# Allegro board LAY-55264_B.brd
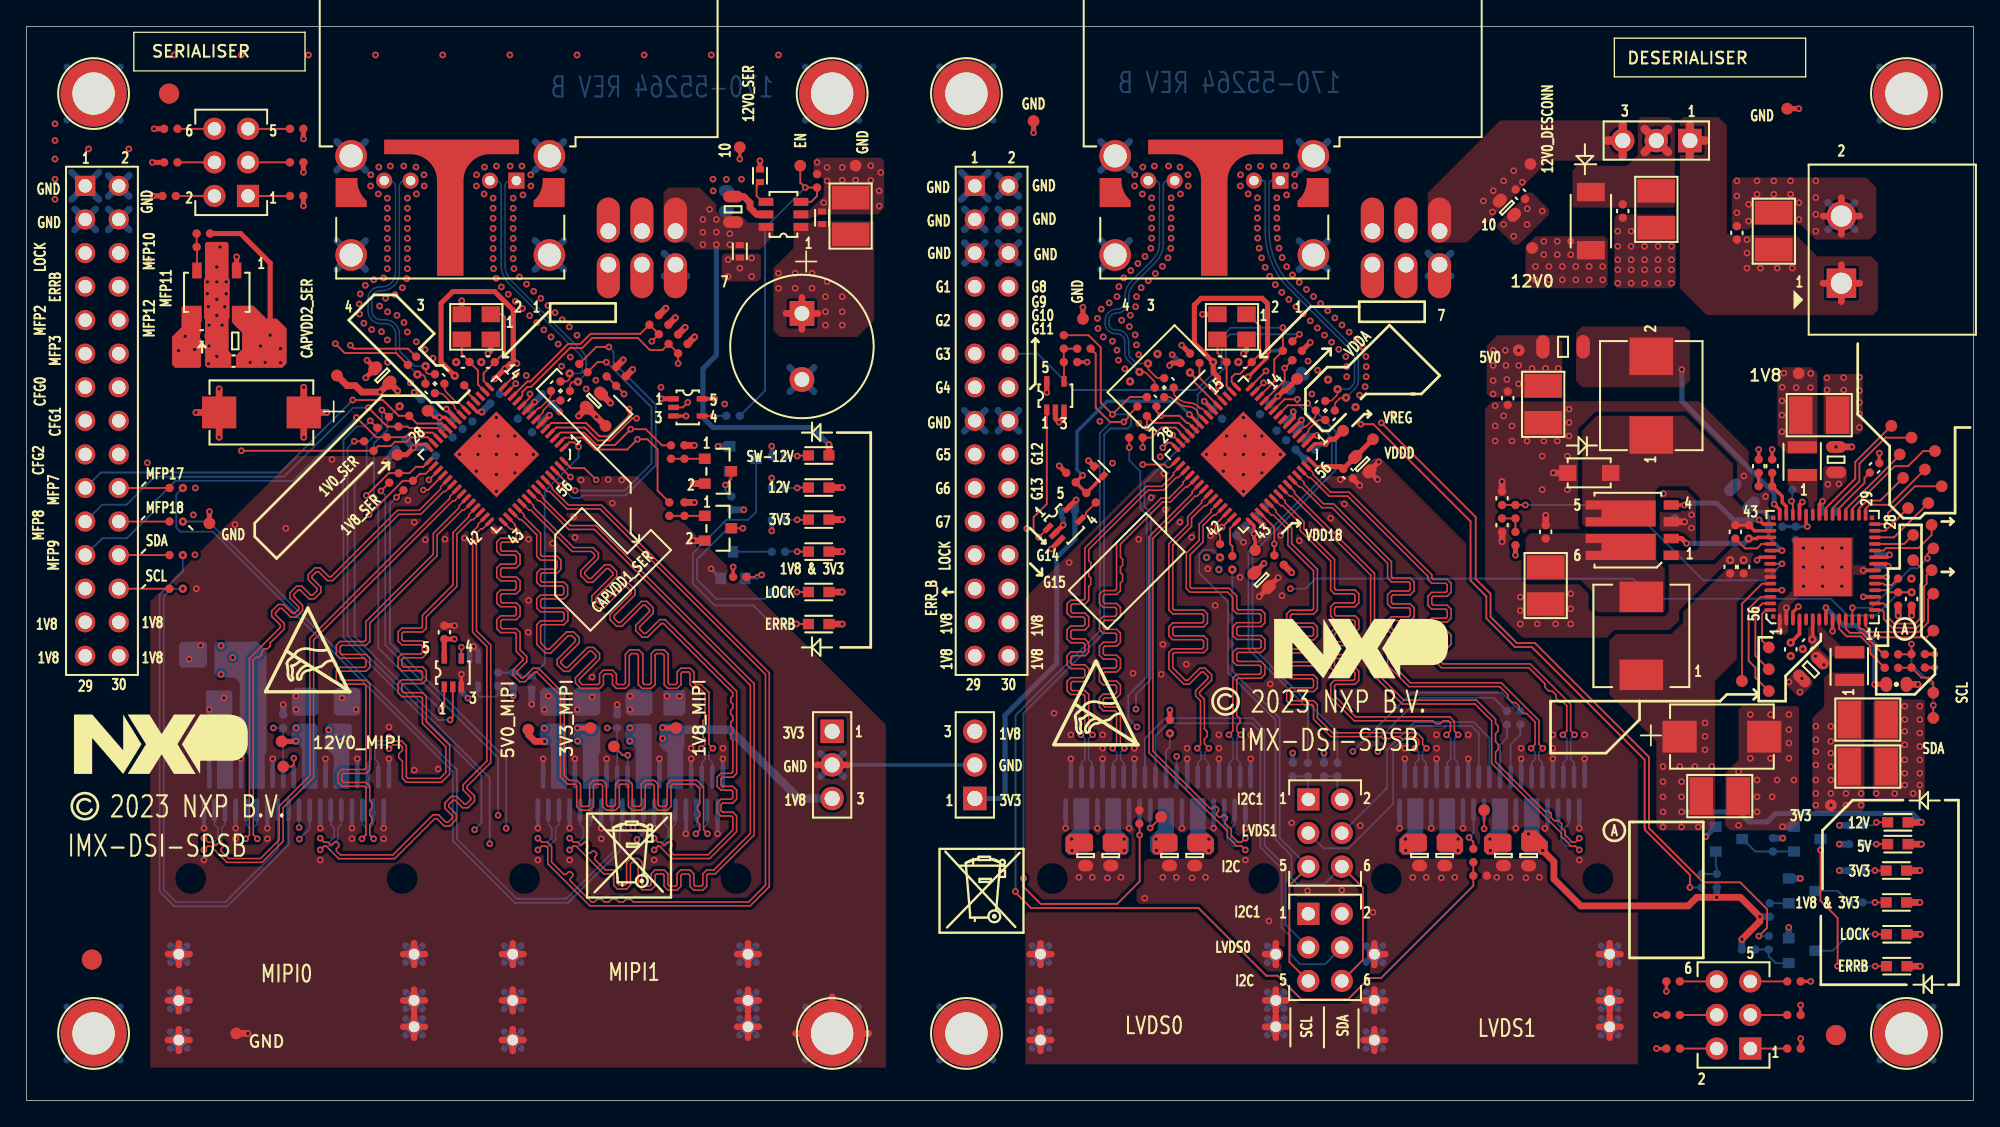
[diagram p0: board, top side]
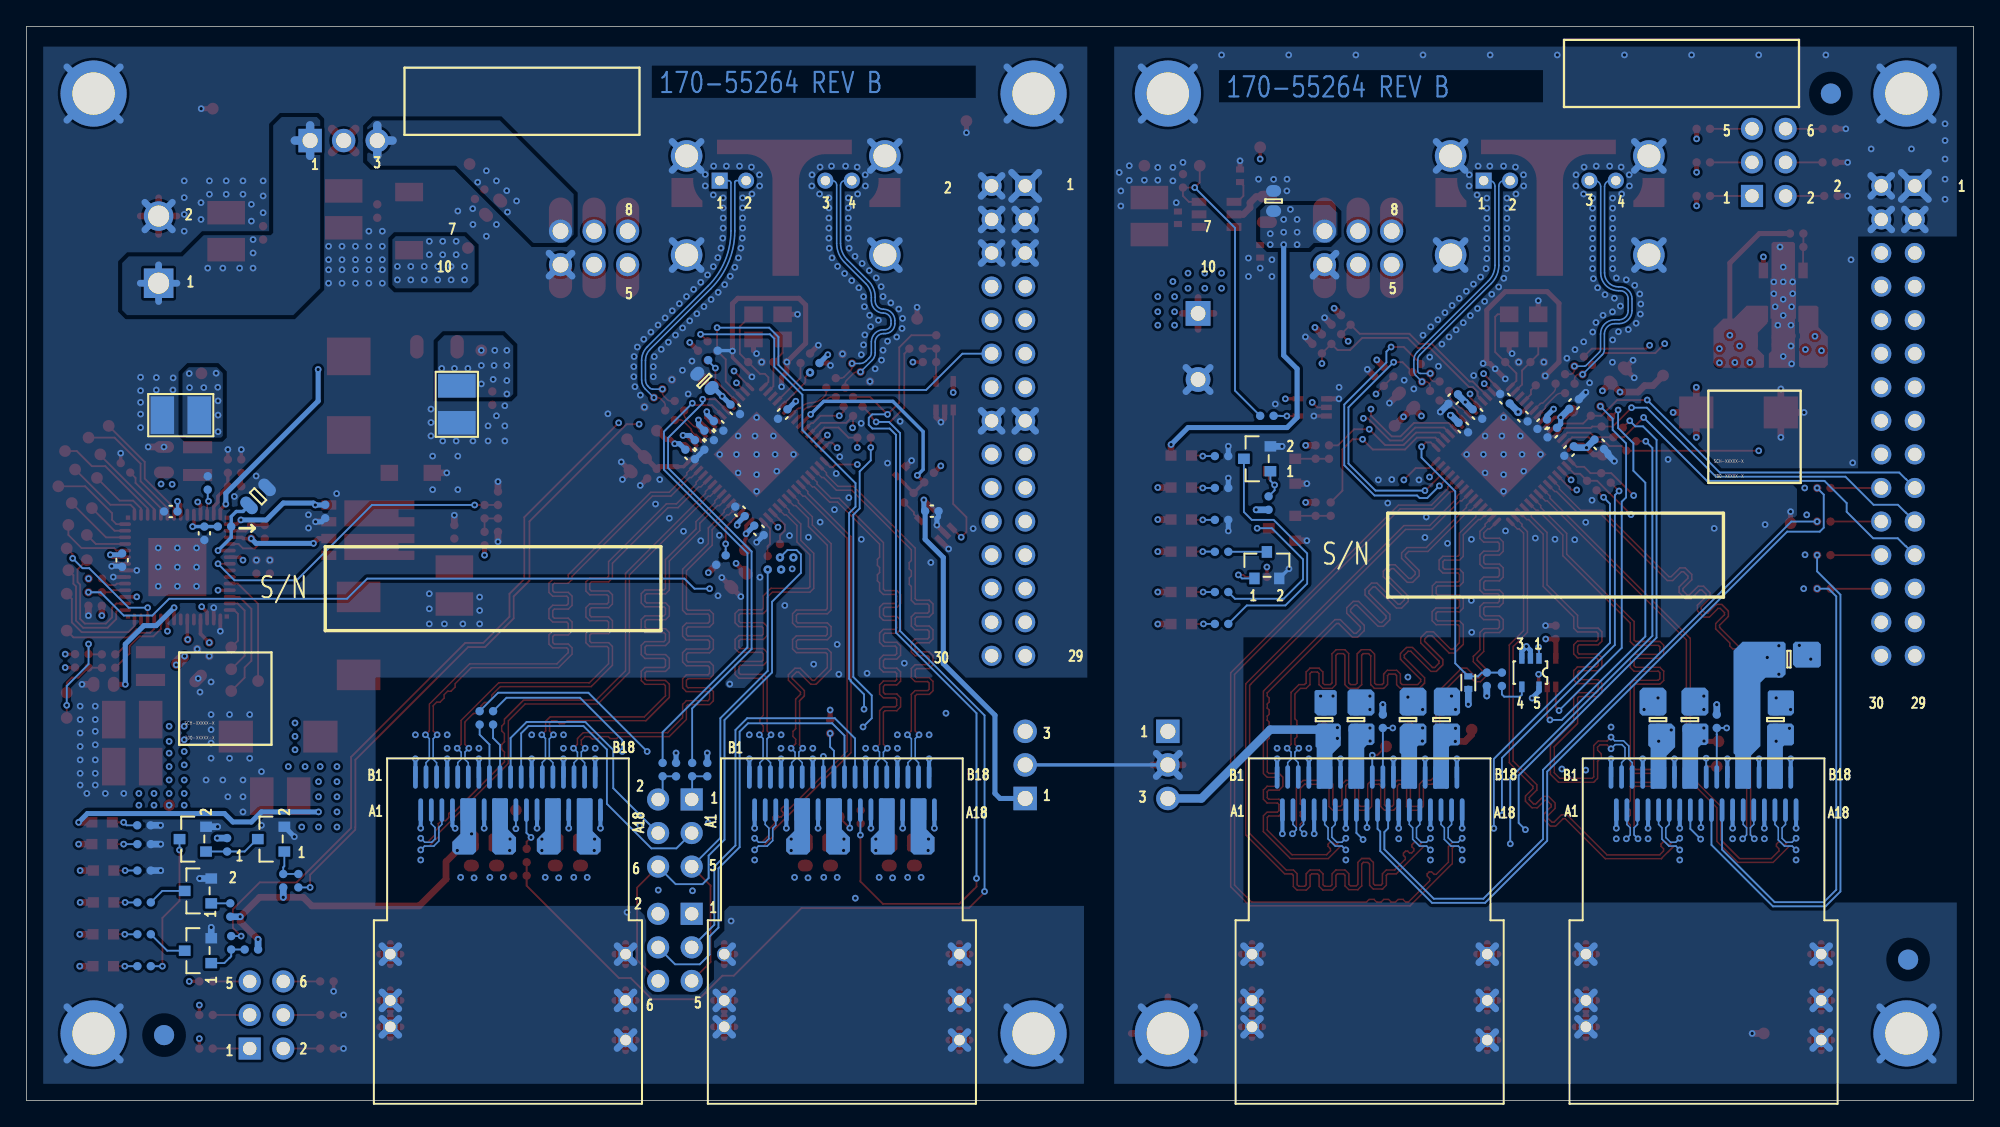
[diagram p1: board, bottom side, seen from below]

Outline 147.32 x 81.28 mm; copper layers: TOP, L2_GND_1, L3_MIX_1, L4_MIX_2, L5_GND_2, BOTTOM. Coordinates in mm from the lower left corner of the outline.
Outline path: 0,81.28 0,0 147.32,0 147.32,81.28 0,81.28

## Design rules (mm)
constraint set DEFAULT: min track width 0.137, pair gap 0.178
net group GMSL2_OUT0_N: nets GMSL2_OUT0_N
net group GMSL2_OUT0_P: nets GMSL2_OUT0_P
net group GMSL2_OUT1_N: nets GMSL2_OUT1_N
net group GMSL2_OUT1_P: nets GMSL2_OUT1_P
net group GRP_DSI0: nets MIPI_DSI0_CLK_N MIPI_DSI0_CLK_P MIPI_DSI0_DATA0_N MIPI_DSI0_DATA0_P MIPI_DSI0_DATA1_N MIPI_DSI0_DATA1_P MIPI_DSI0_DATA2_N MIPI_DSI0_DATA2_P MIPI_DSI0_DATA3_N MIPI_DSI0_DATA3_P
net group GRP_DSI1: nets MIPI_DSI1_CLK_N MIPI_DSI1_CLK_P MIPI_DSI1_DATA0_N MIPI_DSI1_DATA0_P MIPI_DSI1_DATA1_N MIPI_DSI1_DATA1_P MIPI_DSI1_DATA2_N MIPI_DSI1_DATA2_P MIPI_DSI1_DATA3_N MIPI_DSI1_DATA3_P
net group GRP_LVDS0: nets LVDS0_CH0_CLK_N LVDS0_CH0_CLK_P LVDS0_CH0_TX0_N LVDS0_CH0_TX0_P LVDS0_CH0_TX1_N LVDS0_CH0_TX1_P LVDS0_CH0_TX2_N LVDS0_CH0_TX2_P LVDS0_CH0_TX3_N LVDS0_CH0_TX3_P
net group GRP_LVDS1: nets LVDS0_CH1_CLK_N LVDS0_CH1_CLK_P LVDS0_CH1_TX0_N LVDS0_CH1_TX0_P LVDS0_CH1_TX1_N LVDS0_CH1_TX1_P LVDS0_CH1_TX2_N LVDS0_CH1_TX2_P LVDS0_CH1_TX3_N LVDS0_CH1_TX3_P
net group MAX96752_SIOA_N: nets GMSL2DES_OUT0_N
net group MAX96752_SIOB_N: nets GMSL2DES_OUT1_N
net group MAX96752_SIOB_P: nets GMSL2DES_OUT1_P
net group PWR: nets FS84_DBG MAX96789_CAPVDD1 MAX96789_CAPVDD2 VCC_3V3_MIPI VCC_5V0_MIPI VDDA_MAX96752 VDDD_MAX96752

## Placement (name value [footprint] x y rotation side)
BH1  MOUNTING HOLE  [MH_C197-126T]  142.24 5.08 0 top
BH2  MOUNTING HOLE  [MH_C197-126T]  142.24 76.2 0 top
BH3  MOUNTING HOLE  [MH_C197-126T]  5.08 76.2 0 top
BH4  MOUNTING HOLE  [MH_C197-126T]  60.96 76.2 0 top
BH5  MOUNTING HOLE  [MH_C197-126T]  71.12 76.2 0 top
BH6  MOUNTING HOLE  [MH_C197-126T]  5.08 5.08 0 top
BH7  MOUNTING HOLE  [MH_C197-126T]  71.12 5.08 0 top
BH8  MOUNTING HOLE  [MH_C197-126T]  60.96 5.08 0 top
C1  10uF  [CC0603_OV]  49.14 28.83 270 bottom
C2  10uF  [CC0603_OV]  42.79 28.83 270 bottom
C3  10uF  [CC0603_OV]  40.25 28.83 270 bottom
C4  10uF  [CC0603_OV]  46.73 28.83 270 bottom
C5  10uF  [CC0603_OV]  23.88 28.83 270 bottom
C6  10uF  [CC0603_OV]  13.97 33.4 0 bottom
C7  10uF  [CC0603_OV]  14.99 28.83 270 bottom
C8  10uF  [CC0603_OV]  21.46 28.83 270 bottom
C9  0.1uF  [CC0402_25]  31.26 54.61 315 top
C10  0.1uF  [CC0402_25]  30.55 53.89 315 top
C11  0.1uF  [CC0402_25]  40.05 54.05 225 top
C12  0.1uF  [CC0402_25]  40.76 53.34 225 top
C13  10uF  [CC0603_OV]  52.96 68.07 270 bottom
C14  0.1uF  [CC0402_25]  32.64 51.18 315 bottom
C15  10uF  [CC0603_OV]  26.92 54.86 315 top
C16  0.1uF  [CC0402_25]  38.61 50.93 225 bottom
C17  10uF  [CC0603_OV]  42.94 52.96 225 top
C18  15pF  [CC0402_25]  33.02 55.88 180 top
C19  15pF  [CC0402_25]  34.92 55.88 180 top
C20  0.01uF  [CC0402_25]  34.1 51.75 225 bottom
C21  0.1uF  [CC0402_25]  35.46 53.11 45 bottom
C22  0.01uF  [CC0402_25]  37.54 51.95 225 bottom
C23  0.1uF  [CC0402_25]  39.37 53.09 315 bottom
C24  0.01uF  [CC0402_25]  30.61 49.15 315 bottom
C25  0.1uF  [CC0402_25]  28.32 49.66 225 bottom
C26  0.1uF  [CC0402_25]  31.62 35.43 90 top
C27  1uF  [CC0402_TOL0P2]  38.23 31.62 270 bottom
C28  0.01uF  [CC0402_25]  31.88 50.55 315 bottom
C29  0.1uF  [CC0402_25]  30.23 52.7 135 bottom
C30  47uF  [CASE_D]  17.78 52.07 180 top
C31  0.01uF  [CC0402_25]  15.67 55.96 180 top
C32  4.7uF  [CC0805_OV]  15.8 57.48 180 top
C33  2.2uF  [CC0402_25]  13.26 57.86 0 top
C34  0.1uF  [CC0402_25]  86.44 54.31 315 top
C35  0.1uF  [CC0402_25]  85.73 53.59 315 top
C36  0.1uF  [CC0402_25]  97.91 52.58 225 top
C37  0.1uF  [CC0402_25]  98.63 51.86 225 top
C38  10uF  [CC0603_OV]  112.01 67.56 135 top
C39  0.1uF  [CC0402_25]  113.03 68.58 315 top
C40  0.1uF  [CC0402_25]  97.1 48.89 225 bottom
C41  0.1uF  [CC0402_25]  96.39 49.61 225 bottom
C42  0.1uF  [CC0402_25]  78.82 44.6 0 bottom
C43  15pF  [CC0402_25]  92.2 55.88 180 top
C44  15pF  [CC0402_25]  90.3 55.88 180 top
C45  1uF  [CC0402_TOL0P2]  81.15 47.62 135 top
C46  10uF  [CC0603_OV]  101.07 48.16 135 top
C47  0.1uF  [CC0402_25]  99.99 47.44 315 top
C48  10uF  [CC0603_OV]  96.03 54.46 225 bottom
C49  0.1uF  [CC0402_25]  93.69 52.31 225 bottom
C50  10uF  [CC0603_OV]  93.45 39.39 135 top
C51  0.01uF  [CC0402_25]  93.33 44.58 45 bottom
C52  0.01uF  [CC0402_25]  91.9 43.15 225 bottom
C53  0.01uF  [CC0402_25]  95.67 50.33 225 bottom
C54  0.01uF  [CC0402_25]  94.95 51.05 225 bottom
C55  0.01uF  [CC0402_25]  90.1 51.95 315 bottom
C56  10uF  [CC0603_OV]  113.66 18.54 90 top
C57  10uF  [CC0603_OV]  107.31 18.54 90 top
C58  10uF  [CC0603_OV]  105.4 18.54 90 top
C59  10uF  [CC0603_OV]  111.75 18.54 90 top
C60  10uF  [CC0603_OV]  88.39 18.54 90 top
C61  10uF  [CC0603_OV]  82.04 18.54 90 top
C62  10uF  [CC0603_OV]  80.14 18.54 90 top
C63  10uF  [CC0603_OV]  86.49 18.54 90 top
C64  10uF  [CC1210]  123.32 67.44 270 top
C65  0.1uF  [CC0402_25]  120.78 67.31 270 top
C66  10uF  [CC1210]  132.21 65.79 90 top
C67  0.1uF  [CC0402_25]  129.41 65.66 90 top
C68  47uF  [CASE_D]  128.28 27.54 0 top
C69  10uF  [CC1210]  128.12 23.04 0 top
C70  0.1uF  [CC0402_25]  128.91 40.39 90 top
C71  10uF  [CC1210]  114.95 38.97 270 top
C72  0.1uF  [CC0402_25]  114.95 43.04 90 top
C73  0.022uF  [CC0402_25]  111.64 43.54 270 top
C74  0.1uF  [CC0402_25]  111.64 45.58 90 top
C75  22uF  [CC1210]  114.76 52.68 270 bottom
C76  22uF  [CC1210]  114.76 52.68 270 top
C77  0.1uF  [CC0402_25]  112.07 53.15 270 top
C78  4.7uF  [CC0805_OV]  129.79 45.72 315 bottom
C79  0.047uF  [CC0402_25]  129.3 43.04 270 top
C80  1uF  [CC0402_TOL0P2]  60.2 66.8 270 top
C81  10uF  [CC1210]  62.36 66.93 90 top
C82  1000pF  [CC0402_25]  129.92 40.39 90 top
C83  1uF  [CC0402_TOL0P2]  55.5 69.98 90 top
C84  1uF  [CC0402_TOL0P2]  53.98 64.26 270 top
C85  150pF  [CC0402_25]  132.08 48.01 90 top
C86  470uF  [CAP_10P5_RAD]  58.67 59.56 270 top
C87  6800pF  [CC0402_25]  131.06 48.01 90 top
C90  0.1uF  [CC0402_25]  133.49 34.15 90 top
C91  22uF  [CC1210]  139.32 25.27 0 top
C92  22uF  [CC1210]  139.32 28.83 0 top
C93  0.1uF  [CC0402_25]  134.76 34.53 225 top
C94  1000pF  [CC0402_25]  133.86 42.93 270 bottom
C95  4.7uF  [CC0805_OV]  135.01 32.62 225 top
C96  22uF  [CC1210]  135.64 51.86 0 top
C97  22uF  [CC1210]  135.64 51.86 0 bottom
C98  1000pF  [CC0402_25]  139.83 47.88 45 top
C99  4.7uF  [CC0805_OV]  136.92 48.5 90 top
C100  0.1uF  [CC0402_25]  136.4 44.58 0 bottom
C105  0.1uF  [CC0402_25]  140.08 40.89 270 bottom
C106  1000pF  [CC0402_25]  142.63 37.96 90 top
D1  LED GREEN  [LED_0603]  59.94 38.48 180 top
D2  RED LED  [LED_0603]  59.94 36.06 180 top
D3  LED GREEN  [LED_0603]  141.51 12.58 180 top
D4  RED LED  [LED_0603]  141.51 10.17 180 top
D5  PMEG6045ETP  [SOD-128]  118.36 66.55 270 top
D6  NRVTS2H60ESFT3G  [SOD-123]  118.24 47.5 0 top
D7  LED GREEN  [LED_0603]  59.94 41.54 180 top
D8  LED GREEN  [LED_0603]  59.94 46.39 180 top
D9  LED GREEN  [LED_0603]  141.48 14.99 180 top
D10  LED GREEN  [LED_0603]  141.59 21.05 180 top
D11  LED GREEN  [LED_0603]  141.59 19.4 180 top
D12  LED GREEN  [LED_0603]  59.94 48.81 180 top
D13  LED GREEN  [LED_0603]  141.48 17.41 180 top
D14  LED GREEN  [LED_0603]  59.94 43.96 180 top
J1  CON 2X18  [CON2X18_RECEP_WSHELL_0P8_SM_RA]  20.43 12.82 180 bottom
J2  CON 2X18  [CON2X18_RECEP_WSHELL_0P8_SM_RA]  45.69 12.82 180 bottom
J3  99S2HG-40MT5-Z  [CON_99S2HG_40MT5_RA_TH]  37.07 69.61 0 top
J4  HDR_2X15_TH  [HDR215_A_338H]  4.44 69.22 0 top
J5  99S2HG-40MT5-Z  [CON_99S2HG_40MT5_RA_TH]  94.87 69.61 0 top
J6  HDR_2X15_TH  [HDR215_A_338H]  71.75 69.22 0 top
J7  CON 2X18  [CON2X18_RECEP_WSHELL_0P8_SM_RA]  85.62 12.82 180 bottom
J8  CON 2X18  [CON2X18_RECEP_WSHELL_0P8_SM_RA]  110.89 12.82 180 bottom
J9  HDR 1X3  [HDR103_A_344H]  125.86 72.64 270 top
J10  CON 1X2 TB  [CON_TB_1X2_5P08_RA_TH]  137.32 61.85 90 top
J11  HDR 1X3  [HDR103_A_344H]  60.96 27.94 0 top
J12  HDR 1X3  [HDR103_A_344H]  71.75 22.86 180 top
J13  HDR 2X3  [HDR203]  16.76 68.45 180 top
J14  HDR 2X3  [HDR203]  130.43 3.94 180 top
J15  HDR 2X3  [HDR203]  96.99 22.78 0 top
J16  HDR 2X3  [HDR203]  96.99 14.13 0 top
L1  1uH  [IND2_7P4X6P9_SM]  122.18 35.16 90 top
L2  4.7UH  [IND2_7P5X7]  122.94 53.34 90 top
L4  1uH  [IND2520]  137.93 32.88 90 top
L5  1uH  [IND2520]  134.37 48.39 90 top
NOREF  -  []  42.64 14.47 90 top
NOREF#2  -  []  54.59 5.58 90 top
NOREF#3  -  []  51.89 24.49 0 top
NOREF#4  -  []  157.48 55.88 0 top
NOREF#5  -  []  54.59 7.58 90 top
NOREF#6  -  []  80.82 47.96 0 top
NOREF#7  -  []  37.07 69.61 90 top
NOREF#8  -  []  76.72 11.08 90 top
NOREF#9  -  []  139.5 28.77 90 top
NOREF#10  -  []  95.59 -6.47 90 top
NOREF#11  -  []  53.98 63.79 90 top
NOREF#12  -  []  101.83 63.25 0 top
NOREF#13  -  []  106.91 63.25 90 top
NOREF#14  -  []  144.56 77.13 0 top
NOREF#15  -  []  78.62 21.98 0 top
NOREF#16  -  []  39.57 63.98 0 top
NOREF#17  -  []  39.09 24.49 90 top
NOREF#18  -  []  12.43 16.8 90 top
NOREF#19  -  []  137.93 31.83 90 top
NOREF#20  -  []  119.79 11.08 90 top
NOREF#21  -  []  67.91 14.47 90 top
NOREF#22  -  []  132.16 44.11 0 top
NOREF#23  -  []  102.89 16.8 90 top
NOREF#24  -  []  13.83 24.49 90 top
NOREF#25  -  []  83.02 47.45 90 top
NOREF#26  -  []  60.2 66.33 90 top
NOREF#27  -  []  117.49 21.98 0 top
NOREF#28  -  []  5.08 5.08 0 top
NOREF#29  -  []  117.01 68.55 0 top
NOREF#30  -  []  44.03 63.25 90 top
NOREF#31  -  []  104.29 24.49 0 top
NOREF#32  -  []  84.87 69.61 0 top
NOREF#33  -  []  37.69 16.8 90 top
NOREF#34  -  []  73.44 77.13 0 top
NOREF#35  -  []  147.53 45.83 90 top
NOREF#36  -  []  138.32 46.99 90 top
NOREF#37  -  []  139.08 31.48 0 top
NOREF#38  -  []  97.37 63.98 90 top
NOREF#39  -  []  38.23 31.15 90 top
NOREF#40  -  []  122.94 50.36 90 top
NOREF#41  -  []  81.82 47.45 0 top
NOREF#42  -  []  77.62 16.8 90 top
NOREF#43  -  []  11.53 11.08 90 top
NOREF#44  -  []  101.99 11.08 90 top
NOREF#45  -  []  101.83 63.25 90 top
NOREF#46  -  []  119.79 7.58 90 top
NOREF#47  -  []  127.3 -32.82 90 top
NOREF#48  -  []  120.85 -6.47 90 top
NOREF#49  -  []  13.21 80.26 0 top
NOREF#50  -  []  74.93 -34.29 0 top
NOREF#51  -  []  37.69 16.8 90 top
NOREF#52  -  []  120.62 41.89 90 top
NOREF#53  -  []  76.72 4.58 90 top
NOREF#54  -  []  119.79 5.58 90 top
NOREF#55  -  []  125.63 31.46 0 top
NOREF#56  -  []  12.43 16.8 90 top
NOREF#57  -  []  30.39 13.47 90 top
NOREF#58  -  []  137.32 66.93 0 top
NOREF#59  -  []  13.83 24.49 0 top
NOREF#60  -  []  42.64 32.4 90 top
NOREF#61  -  []  12.43 16.8 90 top
NOREF#62  -  []  73.44 6.01 0 top
NOREF#63  -  []  54.82 64.86 90 top
NOREF#64  -  []  38.69 21.98 0 top
NOREF#65  -  []  90.73 30.18 0 top
NOREF#66  -  []  37.69 16.8 90 top
NOREF#67  -  []  -20.32 -257.18 0 top
NOREF#68  -  []  108.6 -5.47 90 top
NOREF#69  -  []  77.62 16.8 0 top
NOREF#70  -  []  109.12 -6.47 90 top
NOREF#71  -  []  54.59 11.08 90 top
NOREF#72  -  []  4.42 22.25 0 top
NOREF#73  -  []  127.14 41.99 90 top
NOREF#74  -  []  95.59 -6.47 90 top
NOREF#75  -  []  90.11 57.6 90 top
NOREF#76  -  []  27.07 69.61 0 top
NOREF#77  -  []  39.09 24.49 0 top
NOREF#78  -  []  36.79 11.08 0 top
NOREF#79  -  []  -285.24 263.14 0 top
NOREF#80  -  []  0 0 0 top
NOREF#81  -  []  102.04 -32.82 90 top
NOREF#82  -  []  94.52 5.58 90 top
NOREF#83  -  []  55.66 13.47 90 top
NOREF#84  -  []  18.11 30.94 0 top
NOREF#85  -  []  122.18 32.21 90 top
NOREF#86  -  []  52.29 21.98 0 top
NOREF#87  -  []  29.33 7.58 90 top
NOREF#88  -  []  11.53 4.58 90 top
NOREF#89  -  []  118.72 78.16 0 top
NOREF#90  -  []  38.58 32.22 0 top
NOREF#91  -  []  94.52 11.08 90 top
NOREF#92  -  []  12.43 16.8 0 top
NOREF#93  -  []  76.72 11.08 0 top
NOREF#94  -  []  119.24 41.99 0 top
NOREF#95  -  []  94.52 7.58 90 top
NOREF#96  -  []  86.87 69.61 0 top
NOREF#97  -  []  37.47 62.38 90 top
NOREF#98  -  []  7.4 77.13 0 top
NOREF#99  -  []  57.05 69.38 90 top
NOREF#100  -  []  92.87 69.61 0 top
NOREF#101  -  []  139.64 36.63 90 top
NOREF#102  -  []  37.69 16.8 0 top
NOREF#103  -  []  13.43 21.98 0 top
NOREF#104  -  []  38.69 21.98 90 top
NOREF#105  -  []  37.69 16.8 90 top
NOREF#106  -  []  7.4 6.01 0 top
NOREF#107  -  []  3.61 24.71 0 top
NOREF#108  -  []  97.37 63.98 90 top
NOREF#109  -  []  80.17 75.35 0 top
NOREF#110  -  []  79.02 24.49 0 top
NOREF#111  -  []  66.04 81.28 0 top
NOREF#112  -  []  133.03 31.46 90 top
NOREF#113  -  []  109.12 -6.47 90 top
NOREF#114  -  []  36.79 4.58 90 top
NOREF#115  -  []  120.62 44.43 0 top
NOREF#116  -  []  0 0 0 top
NOREF#117  -  []  26.63 24.49 0 top
NOREF#118  -  []  134.38 -6.47 90 top
NOREF#119  -  []  95.28 62.38 90 top
NOREF#120  -  []  5.08 5.08 0 top
NOREF#121  -  [unnamed#2]  136.91 4.95 0 top
NOREF#122  -  []  12.43 16.8 90 top
NOREF#123  -  []  59.85 67.4 0 top
NOREF#124  -  []  92.22 21.98 0 top
NOREF#125  -  []  94.87 69.61 90 top
NOREF#126  -  []  135.52 46.99 0 top
NOREF#127  -  []  53.62 64.86 0 top
NOREF#128  -  []  119.71 64.55 90 top
NOREF#129  -  []  117.09 24.49 0 top
NOREF#130  -  []  147.53 58.13 90 top
NOREF#131  -  []  131.5 28.77 0 top
NOREF#132  -  []  35.07 69.61 0 top
NOREF#133  -  []  103.89 21.98 0 top
NOREF#134  -  []  108.6 -5.47 90 top
NOREF#135  -  []  -309.88 -258.44 0 top
NOREF#136  -  []  24.57 63.98 0 top
NOREF#137  -  []  63.28 77.13 0 top
NOREF#138  -  []  55.85 69.38 0 top
NOREF#139  -  []  36.79 11.08 90 top
NOREF#140  -  []  61.05 67.4 90 top
NOREF#141  -  []  83.34 -5.47 90 top
NOREF#142  -  []  69.09 12.7 0 top
NOREF#143  -  []  39.57 63.98 90 top
NOREF#144  -  []  134.37 47.34 90 top
NOREF#145  -  []  5.08 5.08 0 top
NOREF#146  -  []  97.37 63.98 0 top
NOREF#147  -  []  137.32 61.85 90 top
NOREF#148  -  []  42.42 15.37 0 top
NOREF#149  -  []  0 81.28 0 top
NOREF#150  -  []  77.75 26.92 0 top
NOREF#151  -  []  39.57 63.98 90 top
NOREF#152  -  []  29.33 5.58 90 top
NOREF#153  -  []  0 81.28 0 top
NOREF#154  -  [unnamed#2]  4.95 10.67 0 top
NOREF#155  -  []  118.22 50.51 0 top
NOREF#156  -  []  55.5 69.5 90 top
NOREF#157  -  []  124.44 43.8 90 top
NOREF#158  -  []  139.15 36.41 90 top
NOREF#159  -  []  94.41 31.95 0 top
NOREF#160  -  []  134.38 -6.47 90 top
NOREF#161  -  []  118.36 64.35 90 top
NOREF#162  -  []  32.94 57.6 90 top
NOREF#163  -  []  82.37 63.98 0 top
NOREF#164  -  []  22.37 75.35 0 top
NOREF#165  -  []  29.07 69.61 0 top
NOREF#166  -  []  141.88 31.48 90 top
NOREF#167  -  []  11.53 11.08 0 top
NOREF#168  -  []  27.03 21.98 0 top
NOREF#169  -  []  44.03 63.25 0 top
NOREF#170  -  []  83.34 -5.47 90 top
NOREF#171  -  []  103.89 21.98 90 top
NOREF#172  -  []  78.62 21.98 90 top
NOREF#173  -  []  147.32 0 90 top
NOREF#174  -  [unnamed#2]  10.79 76.2 0 top
NOREF#175  -  []  63.28 6.01 0 top
NOREF#176  -  []  67.91 32.4 90 top
NOREF#177  -  []  144.56 6.01 0 top
NOREF#178  -  []  118.22 45.81 90 top
NOREF#179  -  []  135.02 45.83 0 top
NOREF#180  -  []  91.82 24.49 0 top
NOREF#181  -  []  66.04 0 0 top
NOREF#182  -  []  29.33 11.08 90 top
NOREF#183  -  []  13.43 21.98 90 top
NOREF#184  -  []  49.11 63.25 90 top
NOREF#185  -  []  39.78 32.22 90 top
NOREF#186  -  []  118.72 73.08 180 bottom
NOREF#187  -  []  124.71 35.56 180 bottom
NOREF#188  -  []  44.32 38.1 180 bottom
NOREF#189  -  [unnamed#2]  136.91 4.95 180 bottom
NOREF#190  -  []  30.99 75.18 180 bottom
NOREF#191  -  [unnamed#2]  10.79 76.2 180 bottom
NOREF#192  -  [unnamed#2]  4.95 10.67 180 bottom
Q1  BSS138P  [SOT23_A]  52.32 43.31 270 top
Q2  BSS138P  [SOT23_A]  54.2 48.56 90 bottom
Q3  BSS138P  [SOT23_A]  52.32 47.62 270 top
Q4  BSS138P  [SOT23_A]  134.34 11.34 90 bottom
Q5  BSS138P  [SOT23_A]  134.73 19.78 90 bottom
Q6  BSS138P  [SOT23_A]  128.81 19.78 90 bottom
Q7  BUK9K25-40E  [LFPAK56_1P27_4P7X5P3]  121.17 43.16 180 top
Q8  BSS138P  [SOT23_A]  53.47 40.51 180 bottom
Q9  BSS138P  [SOT23_A]  134.34 15.86 90 bottom
R1  48.7K  [RC0402_25]  42.09 54.76 45 top
R2  42.2K  [RC0402_25]  41.47 55.38 45 top
R3  48.7K  [RC0402_25]  29.22 55.31 135 top
R4  42.2K  [RC0402_25]  29.84 55.93 135 top
R5  0  [RC0402_25]  26.9 50.55 135 top
R6  0  [RC0402_25]  25.91 49.53 135 top
R7  0  [RC0402_25]  28.88 46.54 225 top
R8  0  [RC0402_25]  27.81 47.12 225 top
R9  0  [RC0402_25]  11.33 46.35 0 top
R10  0  [RC0402_25]  11.33 41.27 0 top
R11  0  [RC0402_25]  11.33 43.81 0 top
R12  0  [RC0402_25]  11.33 38.73 0 top
R13  402  [RC0402_25]  32.77 54.48 135 top
R14  10.0K  [RC0402_25]  36.83 31.88 90 bottom
R15  0  [RC0402_25]  35.69 31.88 90 bottom
R16  10.0K  [RC0402_25]  44.26 55.16 225 top
R17  44.2K  [RC0402_25]  48.95 57.62 225 top
R18  10.0K  [RC0402_25]  47.49 59.07 225 top
R19  10.0K  [RC0402_25]  44.98 54.44 45 top
R20  56.2K  [RC0402_25]  49.66 56.9 45 top
R21  10.0K  [RC0402_25]  48.21 58.35 45 top
R22  14K  [RC0402_25]  13.39 65.61 180 top
R23  10.0K  [RC0402_25]  49.78 44.75 270 top
R24  10.0K  [RC0402_25]  49.78 49.07 270 top
R25  1.00k  [RC0402_25]  56.9 38.48 0 bottom
R26  1.00k  [RC0402_25]  56.9 36.07 0 bottom
R27  56K  [RC0402_25]  13.39 64.59 0 top
R28  10.0K  [RC0402_25]  53.34 45.21 90 bottom
R29  0  [RC0402_25]  48.64 44.75 270 top
R30  10.0K  [RC0402_25]  84.2 21.46 90 top
R31  0  [RC0402_25]  48.77 49.07 270 top
R33  0  [RC0402_25]  95.43 57.1 45 top
R34  0  [RC0402_25]  90.31 41.6 270 top
R35  0  [RC0402_25]  91.24 40.69 270 top
R36  10.0K  [RC0402_25]  79.03 47.14 315 top
R37  0  [RC0402_25]  80.55 45.61 135 top
R38  402  [RC0402_25]  88.39 56.17 135 top
R39  10.0K  [RC0402_25]  94.78 40.9 135 top
R40  10.0K  [RC0402_25]  96.14 56.38 225 top
R41  10.0K  [RC0402_25]  87.67 55.45 315 bottom
R42  10.0K  [RC0402_25]  94.78 40.9 315 bottom
R43  10.0K  [RC0402_25]  95.38 56.39 135 bottom
R44  10.0K  [RC0402_25]  87.67 55.45 135 top
R45  10.0K  [RC0402_25]  130.3 11.43 0 bottom
R46  10.0K  [RC0402_25]  127.89 16.64 90 bottom
R47  1.00k  [RC0402_25]  138.42 12.58 0 bottom
R48  1.00k  [RC0402_25]  138.42 10.17 0 bottom
R49  10.0K  [RC0402_25]  132.14 19.35 270 bottom
R50  0  [RC0402_25]  131.83 11.94 270 bottom
R51  0  [RC0402_25]  126.75 16.64 90 bottom
R52  0  [RC0402_25]  113.03 28.96 90 bottom
R53  0  [RC0402_25]  112.01 28.96 90 bottom
R54  0  [RC0402_25]  109.47 18.54 90 top
R57  0  [RC0402_25]  112.66 42.53 90 top
R58  5.1K  [RC0402_25]  112.66 44.56 90 top
R59  0.02  [RC1206_OV]  116.26 57.04 180 top
R60  1M  [RC0402_25]  130.31 43.04 270 top
R61  1M  [RC0402_25]  124.71 44.58 270 bottom
R62  10.0K  [RC0402_25]  132.33 43.43 0 bottom
R63  3.57k  [RC0402_25]  131.57 46.48 180 top
R64  22.1K  [RC0402_25]  133.6 46.74 90 bottom
R65  0  [RC0402_25]  141.11 32.75 180 top
R66  0  [RC0402_25]  141.11 33.76 180 top
R67  4.7K  [RC0402_25]  143.13 32.77 180 top
R68  4.7K  [RC0402_25]  143.13 33.78 180 top
R69  0  [RC0402_25]  53.47 51.82 0 bottom
R70  270  [RC0805_OV]  53.47 67.44 270 top
R71  10.0K  [RC0402_25]  19.43 28.7 90 bottom
R72  10.0K  [RC0402_25]  44.69 28.7 90 bottom
R73  4.7K  [RC0402_25]  86.51 28.3 90 top
R74  5.1K  [RC0402_25]  141.62 37.96 90 top
R75  5.1K  [RC0402_25]  142.11 39.5 180 top
R76  4.7K  [RC0402_25]  98.17 25.04 90 bottom
R77  4.7K  [RC0402_25]  95.81 25.04 90 bottom
R78  0  [RC0402_25]  85.14 52.88 135 top
R79  100K  [RC0603_OV]  141.48 31.5 180 top
R80  0  [RC0402_25]  84.42 52.16 135 top
R81  0  [RC0402_25]  27.78 51.36 135 top
R82  0  [RC0402_25]  28.6 52.18 135 top
R83  49.9K  [RC0402_25]  85.22 56.13 45 top
R84  49.9K  [RC0402_25]  83.86 54.77 225 top
R85  49.9K  [RC0402_25]  98.84 54.19 135 top
R86  49.9K  [RC0402_25]  100.2 52.83 315 top
R87  1.00k  [RC0402_25]  56.9 41.53 0 bottom
R88  1.00k  [RC0402_25]  53.98 39.62 180 top
R89  5.23K  [RC0402_25]  56.9 46.35 0 bottom
R90  1.00k  [RC0402_25]  138.42 14.99 0 bottom
R91  5.23K  [RC0402_25]  138.43 20.83 0 bottom
R92  1.00k  [RC0402_25]  131.9 14.42 270 bottom
R93  1.5K  [RC0402_25]  138.42 19.4 0 bottom
R94  5.23K  [RC0402_25]  56.9 48.77 0 bottom
R95  1.00k  [RC0402_25]  138.42 17.41 0 bottom
R96  1.00k  [RC0402_25]  56.9 43.94 0 bottom
R97  10.0K  [RC0402_25]  109.98 17.02 0 top
R98  1.00k  [RC0402_25]  20.45 68.45 180 top
R99  10.0K  [RC0402_25]  10.79 68.45 180 top
R100  1.00k  [RC0402_25]  20.45 70.99 180 top
R101  10.0K  [RC0402_25]  124.59 3.94 180 top
R102  10.0K  [RC0402_25]  124.59 6.48 180 top
R103  10.0K  [RC0402_25]  124.59 9.02 180 top
R104  1.00k  [RC0402_25]  133.73 3.94 180 top
R105  1.00k  [RC0402_25]  133.73 6.48 180 top
R106  1.00k  [RC0402_25]  133.73 9.02 180 top
R107  10.0K  [RC0402_25]  10.92 70.99 180 top
R108  1.00k  [RC0402_25]  20.45 73.53 180 top
R109  10.0K  [RC0402_25]  10.92 73.53 180 top
R110  0  [RC0402_25]  78.49 57.4 270 top
R111  0  [RC0402_25]  80.01 56.9 180 top
R112  1.00k  [RC0402_25]  78.99 55.88 0 top
R114  0  [RC0402_25]  83.95 50.16 180 top
R115  10.0K  [RC0402_25]  59.82 69.6 90 top
R116  4.7K  [RC0402_25]  89.8 41.1 180 bottom
R117  4.7K  [RC0402_25]  90.73 40.18 180 bottom
R118  0  [RC0402_25]  99.19 25.04 270 bottom
R119  0  [RC0402_25]  96.95 25.04 270 bottom
TP1  TP_35MIL  [TESTPOINT_35MIL]  101.88 50.04 135 top
TP2  TP_35MIL  [TESTPOINT_35MIL]  96.14 54.61 135 top
TP3  TP_35MIL  [TESTPOINT_35MIL]  113.79 70.87 90 top
TP4  TP_35MIL  [TESTPOINT_35MIL]  13.84 43.69 0 top
TP5  TP_35MIL  [TESTPOINT_35MIL]  113.92 64.52 0 top
TP6  TP_35MIL  [TESTPOINT_35MIL]  133.22 75.06 0 top
TP7  TP_35MIL  [TESTPOINT_35MIL]  15.88 5.08 0 top
TP8  TP_35MIL  [TESTPOINT_35MIL]  62.74 70.74 90 top
TP9  TP_35MIL  [TESTPOINT_35MIL]  76.2 74.12 0 top
TP10  TP_35MIL  [TESTPOINT_35MIL]  79.93 59.15 0 top
TP11  TP_35MIL  [TESTPOINT_35MIL]  112.9 56.77 270 top
TP13  TP_35MIL  [TESTPOINT_35MIL]  136.53 22.35 90 top
TP14  TP_35MIL  [TESTPOINT_35MIL]  134.08 55.03 45 top
TP15  TP_35MIL  [TESTPOINT_35MIL]  144.27 30.86 90 top
TP16  TP_35MIL  [TESTPOINT_35MIL]  53.98 72.14 180 top
TP17  TP_35MIL  [TESTPOINT_35MIL]  144.27 28.96 90 top
TP18  TP_35MIL  [TESTPOINT_35MIL]  30.35 52.2 135 top
TP19  TP_35MIL  [TESTPOINT_35MIL]  28.07 48.87 135 top
TP20  TP_35MIL  [TESTPOINT_35MIL]  43.81 51.05 135 top
TP21  TP_35MIL  [TESTPOINT_35MIL]  23.49 54.86 135 top
TP22  TP_35MIL  [TESTPOINT_35MIL]  92.96 41.66 135 top
TP23  TP_35MIL  [TESTPOINT_35MIL]  99.62 50.69 135 top
TP24  TP_35MIL  [TESTPOINT_35MIL]  58.55 70.74 180 top
TP25  TP_35MIL  [TESTPOINT_35MIL]  19.43 25.27 0 top
TP26  TP_35MIL  [TESTPOINT_35MIL]  85.85 21.46 0 top
TP27  TP_35MIL  [TESTPOINT_35MIL]  44.45 26.8 0 top
TP28  TP_35MIL  [TESTPOINT_35MIL]  110.29 21.98 0 top
TP29  TP_35MIL  [TESTPOINT_35MIL]  129.79 31.75 0 top
TP30  TP_35MIL  [TESTPOINT_35MIL]  131.83 30.99 0 top
TP31  TP_35MIL  [TESTPOINT_35MIL]  131.83 32.64 0 top
TP32  TP_35MIL  [TESTPOINT_35MIL]  131.83 34.29 0 top
TP33  TP_35MIL  [TESTPOINT_35MIL]  144.27 41.78 0 top
TP34  TP_35MIL  [TESTPOINT_35MIL]  144.27 35.56 0 top
TP35  TP_35MIL  [TESTPOINT_35MIL]  144.27 38.35 0 top
TP36  TP_35MIL  [TESTPOINT_35MIL]  144.15 40.13 0 top
TP37  TP_35MIL  [TESTPOINT_35MIL]  142.75 40.89 0 top
TP38  TP_35MIL  [TESTPOINT_35MIL]  144.15 43.56 0 top
TP39  TP_35MIL  [TESTPOINT_35MIL]  142.75 42.8 0 top
TP40  TP_35MIL  [TESTPOINT_35MIL]  143.89 45.21 0 top
TP41  TP_35MIL  [TESTPOINT_35MIL]  142.37 44.83 0 top
TP42  TP_35MIL  [TESTPOINT_35MIL]  144.91 46.48 0 top
TP43  TP_35MIL  [TESTPOINT_35MIL]  143.64 47.75 0 top
TP44  TP_35MIL  [TESTPOINT_35MIL]  141.99 47.12 0 top
TP45  TP_35MIL  [TESTPOINT_35MIL]  144.4 49.15 0 top
TP46  TP_35MIL  [TESTPOINT_35MIL]  141.73 48.89 0 top
TP47  TP_35MIL  [TESTPOINT_35MIL]  142.62 50.16 0 top
TP48  TP_35MIL  [TESTPOINT_35MIL]  141.1 51.05 0 top
TP49  TP_35MIL  [TESTPOINT_35MIL]  49.15 28.19 0 top
TP50  TP_35MIL  [TESTPOINT_35MIL]  42.67 28.19 0 top
TP51  TP_35MIL  [TESTPOINT_35MIL]  37.97 28.07 0 top
TP52  TP_35MIL  [TESTPOINT_35MIL]  19.3 27.18 0 top
U1  MAX96789GTN/V+T  [QFN56_0P5_8X8_EP4P6]  35.56 48.89 225 top
U2  74AUP1G32GW-Q100  [SC70-5]  32.26 32.38 0 top
U3  AP7361C  [SOT-89-5]  14.4 61.16 180 top
U4  MAX96752GTN/V+T  [QFN56_0P5_8X8_EP4P6]  92.08 48.89 225 top
U5  74AUP1G125GW  [SC70-5]  78.53 43.64 315 top
U6  PC33VR5500W5ES  [QFN56_0P5_8X8_EP4P39]  135.9 40.37 90 top
U7  74AUP1G125GW  [SC70-5]  77.85 53.34 0 top
U8  74AUP1G125GW  [SC70-5]  33.53 32.38 0 bottom
U9  74AUP1G125GW  [SC70-5]  50.04 52.45 270 top
U10  TPS22810DBVT  [SOT23-6]  57.28 67.06 90 top
X1  25 MHz  [OSC4_3P2X2P5_SM]  34.04 58.55 180 top
X2  25 MHz  [OSC4_3P2X2P5_SM]  91.21 58.55 180 top

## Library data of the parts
BH1-BH8 = MOUNT_HOLE
C1-C3 C5-C7 C14-C29 C31-C33 C39-C58 C60-C62 C64-C67 C69-C79 C81-C85 C87 C90-C100 C105 C106 = CAP_NP
C4 C8 C13 C38 C59 C63 C80 = CAP_NP: tolerance: 20%
C9-C12 C34-C37 = CAP_NP: signal model: CAP_NP_CC0402_25_DISCRETE_0.55MM_150-79461_0.1UF_0.1uF
C30 C68 C86 = CAP_POL
D1-D4 D7-D14 = LED
D5 D6 = DIODE_SCHTKY
J1 J2 J7 J8 = CON_2X18_SH6
J3 J5 = CON14_RA_TH
J4 J6 = CONN_HDR_15X2
J9 J11 J12 = CONN_HDR_3X1
J10 = CONN_HDR_1X2
J13-J16 = CONN_HDR_3X2
L1 = INDP: tolerance: 20%
L2 = INDUCTOR
L4 L5 = INDUCTOR: tolerance: 20%
Q1-Q6 Q8 Q9 = MOSFET_N
Q7 = NMOS_DUAL_8P
R1-R31 R33-R54 R57 R59-R73 R75-R112 R114-R119 = RES
R58 R74 = RES: tolerance: 5%
TP1-TP11 TP13-TP52 = T POINT R: Tolerance: TOLERANCE; User Part Number: 510-75618
U1 = MAX96789GTN
U2 = 74AUP1G32_5P
U3 = AP7361C_5P
U4 = MAX96752GTN
U5 U7-U9 = 1G125
U6 = VR5500_56P_EP_A
U10 = TPS22810_6P
X1 X2 = XTAL_4P_B

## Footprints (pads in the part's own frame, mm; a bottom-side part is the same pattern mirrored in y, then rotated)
CAP_10P5_RAD
  rect 1.88x1.88 hole 1.118: 1(0,0)
  round 1.88 hole 1.118: 2(5,0)
CASE_D
  rect 2.591x2.413 smd: 1(-3.2,0) 2(3.2,0)
CC0402_25
  round 0.635 smd: 1(-0.508,0) 2(0.508,0)
CC0402_TOL0P2
  rect 0.457x0.61 smd: 1(-0.475,0) 2(0.475,0)
CC0603_OV
  oval 0.889x1.143 smd: 1(-0.762,0) 2(0.762,0)
CC0805_OV
  oval 0.889x1.524 smd: 1(-0.965,0) 2(0.965,0)
CC1210
  rect 1.778x2.845 smd: 1(-1.397,0) 2(1.397,0)
CON2X18_RECEP_WSHELL_0P8_SM_RA
  round 0 hole 1.549 unplated: (-8,3.975) (8,3.975)
  round 1.092 hole 0.813: 1(-8.9,-1.745) 2(8.9,-1.745) 3(-8.9,-5.245) 4(8.9,-5.245) 5(-8.9,-7.245) 6(8.9,-8.245)
  oval 0.356x1.778 smd: A1(-6.6,9.155) A2(-5.8,9.155) A3(-5,9.155) A4(-4.2,9.155) A5(-3.4,9.155) A6(-2.6,9.155) A7(-1.8,9.155) A8(-1,9.155) A9(-0.2,9.155) A10(0.6,9.155) A11(1.4,9.155) A12(2.2,9.155) A13(3,9.155) A14(3.8,9.155) A15(4.6,9.155) A16(5.4,9.155) A17(6.2,9.155) A18(7,9.155) B1(-7,11.665) B2(-6.2,11.665) B3(-5.4,11.665) B4(-4.6,11.665) B5(-3.8,11.665) B6(-3,11.665) B7(-2.2,11.665) B8(-1.4,11.665) B9(-0.6,11.665) B10(0.2,11.665) B11(1,11.665) B12(1.8,11.665) B13(2.6,11.665) B14(3.4,11.665) B15(4.2,11.665) B16(5,11.665) B17(5.8,11.665) B18(6.6,11.665)
CON_99S2HG_40MT5_RA_TH
  rect 1.219x1.219 hole 0.711: 1(0,0)
  round 1.219 hole 0.711: 2(-2,0) 3(-8,0) 4(-10,0)
  oval 1.753x3.404 hole 1.194: 5(6.96,-6.36) 6(9.5,-6.36) 7(12.04,-6.36) 8(6.96,-3.82) 9(9.5,-3.82) 10(12.04,-3.82)
  round 2.388 hole 1.753: 11(2.5,1.87) 12(-12.5,1.87) 13(-12.5,-5.63) 14(2.5,-5.63)
CON_TB_1X2_5P08_RA_TH
  rect 2.235x2.235 hole 1.6: 1(0,0)
  round 2.235 hole 1.6: 2(5.08,0)
HDR103_A_344H
  rect 1.778x1.778 hole 1.143: 1(0,0)
  round 1.778 hole 1.143: 2(0,-2.54) 3(0,-5.08)
HDR203
  rect 1.676x1.676 hole 1.016: 1(0,0)
  round 1.676 hole 1.016: 2(2.54,0) 3(0,-2.54) 4(2.54,-2.54) 5(0,-5.08) 6(2.54,-5.08)
HDR215_A_338H
  rect 1.524x1.524 hole 1.016: 1(0,0)
  round 1.524 hole 1.016: 2(2.54,0) 3(0,-2.54) 4(2.54,-2.54) 5(0,-5.08) 6(2.54,-5.08) 7(0,-7.62) 8(2.54,-7.62) 9(0,-10.16) 10(2.54,-10.16) 11(0,-12.7) 12(2.54,-12.7) 13(0,-15.24) 14(2.54,-15.24) 15(0,-17.78) 16(2.54,-17.78) 17(0,-20.32) 18(2.54,-20.32) 19(0,-22.86) 20(2.54,-22.86) 21(0,-25.4) 22(2.54,-25.4) 23(0,-27.94) 24(2.54,-27.94) 25(0,-30.48) 26(2.54,-30.48) 27(0,-33.02) 28(2.54,-33.02) 29(0,-35.56) 30(2.54,-35.56)
IND2_7P4X6P9_SM
  rect 2.311x3.302 smd: 1(-2.95,0) 2(2.95,0)
IND2_7P5X7
  rect 2.845x3.302 smd: 1(-2.975,0) 2(2.975,0)
IND2520
  rect 0.914x2.21 smd: 1(-1.05,0) 2(1.05,0)
LED_0603
  rect 0.838x0.787 smd: A(-0.775,0) C(0.775,0)
LFPAK56_1P27_4P7X5P3
  rect 1.143x0.711 smd: 1(-3.275,1.905) 2(-3.275,0.635) 3(-3.275,-0.635) 4(-3.275,-1.905)
  custom 0.493x0.493 smd: 5(0.55,-1.27) 6(0.55,1.27)
MH_C197-126T
  round 5.004 hole 3.2: 1(0,0)
OSC4_3P2X2P5_SM
  rect 1.397x1.194 smd: 1(-1.1,-0.95) 2(1.1,-0.95) 3(1.1,0.95) 4(-1.1,0.95)
QFN56_0P5_8X8_EP4P6
  oval 0.838x0.279 smd: 1(-3.969,3.25) 14(-3.969,-3.25) 29(3.969,-3.25) 42(3.969,3.25)
  rect 0.838x0.279 smd: 2(-3.969,2.75) 3(-3.969,2.25) 4(-3.969,1.75) 5(-3.969,1.25) 6(-3.969,0.75) 7(-3.969,0.25) 8(-3.969,-0.25) 9(-3.969,-0.75) 10(-3.969,-1.25) 11(-3.969,-1.75) 12(-3.969,-2.25) 13(-3.969,-2.75) 30(3.969,-2.75) 31(3.969,-2.25) 32(3.969,-1.75) 33(3.969,-1.25) 34(3.969,-0.75) 35(3.969,-0.25) 36(3.969,0.25) 37(3.969,0.75) 38(3.969,1.25) 39(3.969,1.75) 40(3.969,2.25) 41(3.969,2.75)
  oval 0.279x0.838 smd: 15(-3.25,-3.969) 28(3.25,-3.969) 43(3.25,3.969) 56(-3.25,3.969)
  rect 0.279x0.838 smd: 16(-2.75,-3.969) 17(-2.25,-3.969) 18(-1.75,-3.969) 19(-1.25,-3.969) 20(-0.75,-3.969) 21(-0.25,-3.969) 22(0.25,-3.969) 23(0.75,-3.969) 24(1.25,-3.969) 25(1.75,-3.969) 26(2.25,-3.969) 27(2.75,-3.969) 44(2.75,3.969) 45(2.25,3.969) 46(1.75,3.969) 47(1.25,3.969) 48(0.75,3.969) 49(0.25,3.969) 50(-0.25,3.969) 51(-0.75,3.969) 52(-1.25,3.969) 53(-1.75,3.969) 54(-2.25,3.969) 55(-2.75,3.969)
  rect 4.597x4.597 smd: 57(0,0)
QFN56_0P5_8X8_EP4P39
  rect 0.33x0.33 smd: (-3.738,3.738) (-3.738,-3.738) (3.738,3.738) (3.738,-3.738)
  oval 0.914x0.279 smd: 1(-3.962,3.25) 2(-3.962,2.75) 3(-3.962,2.25) 4(-3.962,1.75) 5(-3.962,1.25) 6(-3.962,0.75) 7(-3.962,0.25) 8(-3.962,-0.25) 9(-3.962,-0.75) 10(-3.962,-1.25) 11(-3.962,-1.75) 12(-3.962,-2.25) 13(-3.962,-2.75) 14(-3.962,-3.25) 29(3.962,-3.25) 30(3.962,-2.75) 31(3.962,-2.25) 32(3.962,-1.75) 33(3.962,-1.25) 34(3.962,-0.75) 35(3.962,-0.25) 36(3.962,0.25) 37(3.962,0.75) 38(3.962,1.25) 39(3.962,1.75) 40(3.962,2.25) 41(3.962,2.75) 42(3.962,3.25)
  oval 0.279x0.914 smd: 15(-3.25,-3.962) 16(-2.75,-3.962) 17(-2.25,-3.962) 18(-1.75,-3.962) 19(-1.25,-3.962) 20(-0.75,-3.962) 21(-0.25,-3.962) 22(0.25,-3.962) 23(0.75,-3.962) 24(1.25,-3.962) 25(1.75,-3.962) 26(2.25,-3.962) 27(2.75,-3.962) 28(3.25,-3.962) 43(3.25,3.962) 44(2.75,3.962) 45(2.25,3.962) 46(1.75,3.962) 47(1.25,3.962) 48(0.75,3.962) 49(0.25,3.962) 50(-0.25,3.962) 51(-0.75,3.962) 52(-1.25,3.962) 53(-1.75,3.962) 54(-2.25,3.962) 55(-2.75,3.962) 56(-3.25,3.962)
  rect 4.394x4.394 smd: 57(0,0)
RC0402_25
  round 0.635 smd: 1(-0.508,0) 2(0.508,0)
RC0603_OV
  oval 0.889x1.143 smd: 1(-0.762,0) 2(0.762,0)
RC0805_OV
  oval 0.889x1.524 smd: 1(-0.965,0) 2(0.965,0)
RC1206_OV
  oval 1.016x1.778 smd: 1(-1.524,0) 2(1.524,0)
SC70-5
  rect 0.406x0.813 smd: 1(-0.65,-1.079) 2(0,-1.079) 3(0.65,-1.079) 4(0.65,1.079) 5(-0.65,1.079)
SOD-123
  rect 1.321x1.219 smd: A(-1.626,0) C(1.626,0)
SOD-128
  rect 1.397x2.108 smd: A(-2.2,0) C(2.2,0)
SOT23-6
  rect 0.61x1.118 smd: 1(-0.95,-1.321) 2(0,-1.321) 3(0.95,-1.321) 4(0.95,1.321) 5(0,1.321) 6(-0.95,1.321)
SOT23_A
  rect 0.787x0.889 smd: 1(-0.94,-1.003) 2(0.94,-1.003) 3(0,1.003)
SOT-89-5
  rect 0.711x1.194 smd: 1(-1.5,-1.65) 3(1.5,-1.65) 4(1.5,1.65) 5(-1.5,1.65)
  custom 0.482x0.482 smd: 2(0,-0.122)
TESTPOINT_35MIL
  round 0.889 smd: 1(0,0)
unnamed#2
  round 1.524 smd: (0,0)

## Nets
12V0SER_LOADSW_EN: R69.2 R115.1 TP24.1(TP) U10.3
GND: BH1.1 BH2.1 BH3.1 BH4.1 BH5.1 BH6.1 BH7.1 BH8.1 C1.1 C2.1 C3.1 C4.1 C5.1 C6.1 C7.1 C8.1 C13.1 C14.2 C15.1 C16.2 C17.1 C18.2 C19.2 C20.2 C21.2 C22.2 C23.2 C24.2 C25.2 C26.2 C27.2 C28.2 C29.2 C30.2 C31.2 C32.2 C33.2 C38.1 C39.2 C40.2 C41.2 C42.1 C43.2 C44.2 C45.2 C46.1 C47.2 C48.1 C49.2 C50.1 C51.2 C52.2 C53.2 C54.2 C55.2 C56.1 C57.1 C58.1 C59.1 C60.1 C61.1 C62.1 C63.1 C64.2 C65.2 C66.2 C67.2 C68.2 C69.2 C70.2 C71.2 C72.2 C73.2 C74.2 C75.2 C76.2 C77.2 C78.1 C80.1 C81.2 C82.2 C83.2 C84.2 C85.2 C86.2 C87.2 C90.1 C91.2 C92.2 C93.2 C94.2 C95.2 C96.2 C97.2 C98.2 C99.2 C100.2 C105.2 C106.1 D6.A J1.1 J1.2 J1.3 J1.4 J1.5 J1.6(SH6) J1.A1 J1.A4 J1.A7 J1.A12 J1.A15 J1.A18 J1.B1 J1.B4 J1.B7 J1.B12 J1.B15 J1.B18 J2.1 J2.2 J2.3 J2.4 J2.5 J2.6(SH6) J2.A1 J2.A4 J2.A7 J2.A12 J2.A15 J2.A18 J2.B1 J2.B4 J2.B7 J2.B12 J2.B15 J2.B18 J3.7 J3.11 J3.12 J3.13 J3.14(SH4) J4.1 J4.2 J4.3 J4.4 J5.7 J5.11 J5.12 J5.13 J5.14(SH4) J6.1 J6.2 J6.3 J6.4 J6.5 J6.6 J6.15 J6.16 J7.1 J7.2 J7.3 J7.4 J7.5 J7.6(SH6) J7.A1 J7.A4 J7.A7 J7.A12 J7.A15 J7.A18 J7.B1 J7.B4 J7.B7 J7.B12 J7.B15 J7.B18 J8.1 J8.2 J8.3 J8.4 J8.5 J8.6(SH6) J8.A1 J8.A4 J8.A7 J8.A12 J8.A15 J8.A18 J8.B1 J8.B4 J8.B7 J8.B12 J8.B15 J8.B18 J10.2(B1) J11.2 J12.2 Q1.2(SOURCE) Q2.2(SOURCE) Q3.2(SOURCE) Q4.2(SOURCE) Q5.2(SOURCE) Q6.2(SOURCE) Q7.3(SOURCE2) Q8.2(SOURCE) Q9.2(SOURCE) R13.2 R19.2 R20.2 R21.2 R27.2 R30.2 R38.2 R42.2 R43.2 R44.2 R61.2 R64.2 R71.2 R72.2 R79.1 R83.2 R84.2 R85.2 R86.2 R89.1 R91.1 R93.1 R94.1 R95.1 R96.1 R97.2 R99.2 R101.2 R102.2 R103.2 R107.2 R109.2 R115.2 TP4.1(TP) TP6.1(TP) TP7.1(TP) TP8.1(TP) TP9.1(TP) TP10.1(TP) U1.57 U2.3 U3.2 U4.57 U5.2 U5.3 U6.1(WAKE2) U6.2 U6.20 U6.21 U6.22 U6.57 U7.2 U7.3 U8.2 U8.3 U9.1 U9.3 U10.2 X1.2 X1.4 X2.2 X2.4
VCC_1V0_SER: C28.1 C29.1 C30.1 C31.1 C32.1 R22.1 TP18.1(TP) U1.23 U3.5(OUT)
VCC_1V8_LVDS: C40.1 C41.1 C50.2 C51.1 C52.1 C53.1 C54.1 C55.1 C56.2 C60.2 C96.1 C97.1 J6.27 J6.28 J6.29 J6.30 J7.A5 J7.A6 J8.A5 J8.A6 J12.3 L5.2 R36.1 R39.1 R40.1 R41.1 R45.1 R46.1 R73.2 R76.2 R77.2 R92.2 R104.1 R105.1 R106.1 R112.2 R116.2 R117.2 TP14.1(TP) TP22.1(TP) TP23.1(TP) U4.1 U4.2 U4.5 U4.6 U4.20 U4.43 U4.44 U6.17 U6.39
VCC_1V8_MIPI: C1.2 C5.2 C20.1 C21.1 C22.1 C23.1 C24.1 C25.1 C26.1 C33.1 J1.B5 J1.B6 J2.B5 J2.B6 J4.27 J4.28 J4.29 J4.30 J11.3 R14.1 R16.1 R17.1 R18.1 R23.1 R24.1 R88.2 R98.1 R100.1 R108.1 TP19.1(TP) TP49.1(TP) U1.9 U1.19 U1.28 U2.5 U3.1 U3.4 U8.5 U9.5
VCC_3V3_LVDS: C42.2 C57.2 C61.2 C90.2 C91.1 C92.1 C105.1 D3.A D4.A D9.A D13.A J7.A13 J7.A14 J8.A13 J8.A14 J12.1 L4.1 R49.1 R67.1 R68.1 R74.1 R75.1 TP13.1(TP) U5.5 U6.4 U6.9 U6.23 U7.5
VCC_3V3_MIPI: C2.2 C6.2 D1.A D2.A D7.A D14.A J1.B13 J1.B14 J2.B13 J2.B14 J11.1 R28.1 TP50.1(TP)
VCC_5V0_LVDS: C58.2 C62.2 C75.1 C76.1 C77.1 C93.1 C95.1 C99.1 C100.1 D11.A J7.A16 J7.A17 J8.A16 J8.A17 R59.2 TP11.1(TP) U6.3 U6.6 U6.36 U6.48 U6.53
VCC_5V0_MIPI: C3.2 C7.2 J1.B16 J1.B17 J2.B16 J2.B17 TP51.1(TP)
VCC_12V0: C64.1 C65.1 D5.A J9.2
VCC_12V0_DESCONN: C38.2 C39.1 J5.10 J9.3 TP3.1(TP)
VCC_12V0_EXT: C66.1 C67.1 J9.1 J10.1
VCC_12V0_LVDS: C59.2 C63.2 C68.1 C69.1 C70.1 C82.1 D5.C D10.A J7.A8 J7.A9 J8.A8 J8.A9 L1.1 R57.1 TP5.1(TP) U6.50 U6.51
VCC_12V0_MIPI: C4.2 C8.2 C80.2 C81.1 C86.1 D8.A J1.B8 J1.B9 J2.B8 J2.B9 TP52.1(TP) U10.1
VCC_12V0_SER: C13.2 C84.1 D12.A J3.10 R70.2 TP16.1(TP) U10.6(VOUT)
VDDA_MAX96752: C48.2 C49.1 TP2.1(TP) U4.10
VDDD_MAX96752: C46.2 C47.1 TP1.1(TP) U4.56
FS84_BUCK1_SW: L5.1 U6.37
FS84_BUCK3_SW: L4.2 U6.7
FS84_DBG: R79.2 U6.8
FS84_ERRMON: R64.1 U6.40
FS84_INTB: C98.1 U6.33
FS84_PRE_BOOT: C79.2 U6.46
FS84_PRE_COMP: C85.1 R63.1 U6.41
FS84_PRE_CSP: L2.2 R59.1 U6.42
FS84_PRE_GHS: Q7.2 R60.2 U6.45
FS84_PRE_GLS: Q7.4 R61.1 U6.43
FS84_PRE_SW: C79.1 D6.C L2.1 Q7.1 Q7.5 R60.1 U6.44
FS84_PSYNC: C94.1 R62.2 U6.38
FS84_SCL: R65.2 U6.10
FS84_SDA: R66.2 U6.11
FS84_VBOS: C78.2 R62.1 U6.47
FS84_WAKE1: C74.1 R58.2 U6.49
GMSL2_OUT0_N: C10.1 J3.4 R3.1
GMSL2_OUT0_P: C9.1 J3.3 R4.1
GMSL2_OUT1_N: C12.1 J3.1 R1.1
GMSL2_OUT1_P: C11.1 J3.2 R2.1
GMSL2DES_OUT0_N: C35.1 J5.4 R84.1
GMSL2DES_OUT0_P: C34.1 J5.3 R83.1
GMSL2DES_OUT1_N: C37.1 J5.1 R86.1
GMSL2DES_OUT1_P: C36.1 J5.2 R85.1
LDO_1V0_FB_SER: R22.2 R27.1 U3.3
LVDS0_BL_PWM: J7.B8 R52.2 R114.2
LVDS0_CH0_CLK_N: J7.A2 U4.35
LVDS0_CH0_CLK_P: J7.A3 U4.34
LVDS0_CH0_TS_SCL: J7.B11 J16.3
LVDS0_CH0_TS_SDA: J7.B10 J16.4
LVDS0_CH0_TX0_N: J7.B2 U4.39
LVDS0_CH0_TX0_P: J7.B3 U4.38
LVDS0_CH0_TX1_N: J7.B5 U4.37
LVDS0_CH0_TX1_P: J7.B6 U4.36
LVDS0_CH0_TX2_N: J7.B13 U4.33
LVDS0_CH0_TX2_P: J7.B14 U4.32
LVDS0_CH0_TX3_N: J7.B16 U4.31
LVDS0_CH0_TX3_P: J7.B17 U4.30
LVDS0_CH1_CLK_N: J8.A2 U4.51
LVDS0_CH1_CLK_P: J8.A3 U4.50
LVDS0_CH1_TS_SCL: J8.B11 J15.3
LVDS0_CH1_TS_SDA: J8.B10 J15.4
LVDS0_CH1_TX0_N: J8.B2 U4.55
LVDS0_CH1_TX0_P: J8.B3 U4.54
LVDS0_CH1_TX1_N: J8.B5 U4.53
LVDS0_CH1_TX1_P: J8.B6 U4.52
LVDS0_CH1_TX2_N: J8.B13 U4.49
LVDS0_CH1_TX2_P: J8.B14 U4.48
LVDS0_CH1_TX3_N: J8.B16 U4.47
LVDS0_CH1_TX3_P: J8.B17 U4.46
LVDS0_TS_INT: J7.B9 R33.2 R53.2 R73.1
LVDS_EN_1: J7.A11 R30.1 R78.2 R110.1
LVDS_EN_2: R54.1 R80.2 R97.1 R111.1
MAX96752_ERR_B: J6.25 R51.1 U4.14
MAX96752_GPIO01_I2CSEL: J6.7 R41.2 R44.1 U4.19
MAX96752_GPIO02_MS: J6.9 R39.2 R42.1 U4.45
MAX96752_GPIO03: R34.1 U4.40
MAX96752_GPIO04: J6.13 U4.41
MAX96752_GPIO05: R35.1 U4.42
MAX96752_GPIO06: J6.19 U4.27
MAX96752_GPIO07: J6.21 U4.28
MAX96752_GPIO08: J6.8 U4.29
MAX96752_GPIO09_CXTP: J6.10 R40.2 R43.1 U4.11
MAX96752_GPIO10: J6.12 R33.1 U4.12
MAX96752_GPIO11: J6.14 R78.1 U4.24
MAX96752_GPIO12: J6.18(B9) R80.1 U4.25
MAX96752_GPIO13: J6.20 R114.1 U4.26
MAX96752_GPIO14: R118.1 U4.8
MAX96752_GPIO15: R119.1 U4.9
MAX96752_LOCK: J6.23 R50.1 U4.13
MAX96752_PWDN_B: C45.1 R36.2 R37.2 U4.23
MAX96752_SCL: J15.1 J16.1 R77.1 R119.2
MAX96752_SCL1: J15.5 J16.5 R35.2 R117.1
MAX96752_SDA: J15.2 J16.2 R76.1 R118.2
MAX96752_SDA1: J15.6(B3) J16.6(B3) R34.2 R116.1
MAX96752_SIOA_N: C35.2 U4.22
MAX96752_SIOA_P: C34.2 U4.21
MAX96752_SIOB_N: C37.2 U4.3
MAX96752_SIOB_P: C36.2 U4.4
MAX96752_X1: C43.1 U4.15 X2.1
MAX96752_X2: C44.1 U4.16 X2.3
MAX96752_XRES: R38.1 U4.18(XRES)
MAX96789_CAPVDD1: C16.1 C17.2 TP20.1(TP) U1.6
MAX96789_CAPVDD2: C14.1 C15.2 TP21.1(TP) U1.22
MAX96789_CFG0: J4.13 R16.2 R19.1 U1.10
MAX96789_CFG1: J4.15 R17.2 R20.1 U1.11
MAX96789_CFG2: J4.17 R18.2 R21.1 U1.12
MAX96789_ERRB: J4.7 R31.1 U1.3
MAX96789_I2C-SCL: J4.26 R12.1 U1.14
MAX96789_I2C-SDA: J4.24 R10.1 U1.13
MAX96789_LMN0: R4.2 U1.31
MAX96789_LMN1: R3.2 U1.32
MAX96789_LMN2: R2.2 U1.53
MAX96789_LMN3: R1.2 U1.54
MAX96789_MFP2: J4.9 U1.4
MAX96789_MFP3: J4.11 U1.5
MAX96789_MFP7: J4.19 R82.1 U1.24
MAX96789_MFP8: J4.21 R81.1 U1.25
MAX96789_MFP9: J4.23 R5.1 U1.26
MAX96789_MFP10: J4.6 R6.1 U1.27
MAX96789_MFP11: J4.8 R8.1 U1.29
MAX96789_MFP12: J4.10 R7.1 U1.30
MAX96789_MFP17: J4.20 R9.1 U1.55
MAX96789_MFP18: J4.22 R11.1 U1.56
MAX96789_MS_LOCK: J4.5 R29.1 U1.2
MAX96789_PWDN_B: C27.1 R14.2 R15.2 U1.1(\\P\W\D\N)
MAX96789_SIOA_N: C10.2 U1.21
MAX96789_SIOA_P: C9.2 U1.20
MAX96789_SIOB_N: C12.2 U1.7
MAX96789_SIOB_P: C11.2 U1.8
MAX96789_XRES: R13.1 U1.18
MIPI_DSI0_1_EN: J1.B11 R71.1 R82.2 U2.1
MIPI_DSI0_BL_PWM: J1.A8 R8.2
MIPI_DSI0_CLK_N: J1.B2 U1.40
MIPI_DSI0_CLK_P: J1.B3 U1.39
MIPI_DSI0_DATA0_N: J1.A2 U1.38
MIPI_DSI0_DATA0_P: J1.A3 U1.37
MIPI_DSI0_DATA1_N: J1.A5 U1.42
MIPI_DSI0_DATA1_P: J1.A6 U1.41
MIPI_DSI0_DATA2_N: J1.A13 U1.34
MIPI_DSI0_DATA2_P: J1.A14 U1.33
MIPI_DSI0_DATA3_N: J1.A16 U1.36
MIPI_DSI0_DATA3_P: J1.A17 U1.35
MIPI_DSI0_TS_INT_B: J1.A9 R5.2
MIPI_DSI0_TS_SCL: J1.A11 R12.2
MIPI_DSI0_TS_SDA: J1.A10 R10.2
MIPI_DSI1_1_EN: J2.B11 R72.1 R81.2 U2.2
MIPI_DSI1_BL_PWM: J2.A8 R6.2
MIPI_DSI1_CLK_N: J2.B2 U1.46
MIPI_DSI1_CLK_P: J2.B3 U1.45
MIPI_DSI1_DATA0_N: J2.A2 U1.44
MIPI_DSI1_DATA0_P: J2.A3 U1.43
MIPI_DSI1_DATA1_N: J2.A5 U1.48
MIPI_DSI1_DATA1_P: J2.A6 U1.47
MIPI_DSI1_DATA2_N: J2.A13 U1.50
MIPI_DSI1_DATA2_P: J2.A14 U1.49
MIPI_DSI1_DATA3_N: J2.A16 U1.52
MIPI_DSI1_DATA3_P: J2.A17 U1.51
MIPI_DSI1_TS_INT_B: J2.A9 R7.2
MIPI_DSI1_TS_SCL: J2.A11 R11.2
MIPI_DSI1_TS_SDA: J2.A10 R9.2
MIPI_DSI_EN: U2.4(Y) U8.1 U9.2
PMIC_PG: C106.2 R74.2 U5.1 U6.18 U7.1
PRE_COMP_RC: C87.1 R63.2
SW_CT: C83.1 U10.4
SW_QOD: R70.1 U10.5
VPI: C71.1 C72.1 L1.2 Q7.6
N20060287: C19.1 U1.15 X1.1
N20060288: C18.1 U1.16 X1.3
N20069061: J8.B8 R52.1
N20069073: J8.B9 R53.1
N20082822: D1.C(CATHODE) R25.2
N20082834: Q1.3 R25.1
N20083165: D2.C(CATHODE) R26.2
N20083177: Q2.3 R26.1
N20083959: Q2.1 Q3.3 R28.2
N20084103: Q1.1 R23.2 R29.2
N20084118: Q3.1 R24.2 R31.2
N20098940: R37.1 U5.4(Y)
N20105492: D3.C(CATHODE) R47.2
N20105494: D4.C(CATHODE) R48.2
N20105548: Q4.3 R47.1
N20105560: Q5.3 R48.1
N20105562: Q4.1 R45.2 R50.2
N20105564: Q6.1 R46.2 R51.2
N20105588: Q5.1 Q6.3 R49.2
N20114256: C73.1 R57.2 R58.1
N20115373: R65.1 R67.2 TP15.1(TP)
N20115434: R66.1 R68.2 TP17.1(TP)
N20116336: R75.2 U6.19
N20169094: J8.A11 R54.2
N20198038: R15.1 U8.4(Y)
N20266401: J1.B10 TP25.1(TP)
N20266443: J2.B10 TP27.1(TP)
N20266627: J7.A10 TP26.1(TP)
N20266649: J8.A10 TP28.1(TP)
N20266684: TP29.1(TP) U6.52
N20266708: TP30.1(TP) U6.54
N20266714: TP31.1(TP) U6.55
N20267097: TP32.1(TP) U6.56
N20272842: D7.C(CATHODE) R87.2
N20272854: Q8.3 R87.1
N20272867: Q8.1 R88.1
N20273152: D8.C(CATHODE) R89.2
N20273623: D9.C(CATHODE) R90.2
N20273625: D10.C(CATHODE) R91.2
N20273637: Q9.3 R90.1
N20273680: Q9.1 R92.1
N20273951: D11.C(CATHODE) R93.2
N20274335: D12.C(CATHODE) R94.2
N20274920: D13.C(CATHODE) R95.2
N20275554: D14.C(CATHODE) R96.2
N20319150: J13.2 R99.1
N20319151: J13.4 R107.1
N20319153: J13.6(B3) R109.1
N20319312: J13.5 R108.2
N20319313: J13.3 R100.2
N20319314: J13.1 R98.2
N20319786: J14.1 R104.2
N20319788: J14.2 R101.1
N20319806: J14.3 R105.2
N20319808: J14.4 R102.1
N20319814: J14.5 R106.2
N20319816: J14.6(B3) R103.1
N20331689: R110.2 R111.2 R112.1 U7.4(Y)
N20347583: R69.1 U9.4(Y)
N2022936611: TP33.1(TP) U6.12
N2022936612: TP34.1(TP) U6.13
N2022936613: TP35.1(TP) U6.14
N2022936614: TP36.1(TP) U6.15
N2022936615: TP37.1(TP) U6.16
N2022936623: TP38.1(TP) U6.24
N2022936624: TP39.1(TP) U6.25
N2022936625: TP40.1(TP) U6.26
N2022936626: TP41.1(TP) U6.27
N2022936627: TP42.1(TP) U6.28
N2022936628: TP43.1(TP) U6.29
N2022936629: TP44.1(TP) U6.30
N2022936630: TP45.1(TP) U6.31
N2022936631: TP46.1(TP) U6.32
N2022936633: TP47.1(TP) U6.34
N2022936634: TP48.1(TP) U6.35

Pads without a net: J3 5 6 8 9; J4 12 14 16 18 25; J5 5 6 8 9; J6 11 17 22 24 26; U1 17; U4 7 17; U6 5

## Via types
v1: diameter 0.508, hole 0.257, TOP to BOTTOM, 89 vias
v2: diameter 0.508, hole 0.254, TOP to BOTTOM, 1020 vias

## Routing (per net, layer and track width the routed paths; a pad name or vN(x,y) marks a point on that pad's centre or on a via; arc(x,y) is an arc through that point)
12V0SER_LOADSW_EN: length 24.1
  TOP w0.137: TP24.1 58.55,69.47 v2(58.93,69.09) R115.1 59.82,68.45 59.37,68.01 U10.3
  BOTTOM w0.137: R69.2 55.88,53.72 55.88,66.04 v2(58.93,69.09)
GND: length 1454.1
  TOP w0.254: v2(93.9,56.72) 93.9,56.24 v2(92.43,54.76) ; R102.2 v2(123.33,6.48) ; R27.2 v2(14.64,64.59) ; C87.2 v2(131.06,49.26) ; R101.2 v2(123.33,3.94) ; U9.3 v2(49.91,51.8) ; C98.2 v2(140.19,48.99) ; C85.2 v2(132.08,49.26) ; R103.2 v2(124.08,8.27) ; U2.3 v2(32.91,32.26)
  TOP w0.279: v2(140.87,40.44) 140.69,40.62 U6.22 ; U6.21 v2(138.97,40.12) ; U6.20 v2(140.75,39.62) ; U6.2 v2(133.15,37.29) ; U6.1 v2(132.65,35.52)
  TOP w0.381: R107.2 v2(9.53,70.99) ; R38.2 v2(87.41,57.16) ; v2(34.92,56.52) 35.14,56.74 X1.4 ; X2.4 92.31,56.75 v2(92.08,56.52) ; X1.2 v2(32.94,60.53) ; R99.2 v2(9.54,68.45) ; v2(93.9,56.72) 93.9,60.3 93.5,60.71 88.87,60.71 88.37,60.2 88.37,57.3 v1(89.79,55.88) 89.79,55.12 90.19,54.72 v2(90.19,54.01) ; C26.2 v2(32.38,35.94) ; v2(25.68,54.69) C15.1 v2(25.77,56.02) ; U5.3 v2(77.55,41.74) ; C45.2 v2(80.35,48.43) ; v2(102.32,48.33) C46.1 v2(102.23,47) ; v2(94.71,39.57) C50.1 v2(93.27,38.14) ; R83.2 v1(85.58,56.5) ; X2.2 v2(88.98,59.5) ; TP9.1 v2(76.2,73.24) ; v1(32.41,54.84) 31.37,55.88 31.37,60.32 32.26,61.21 35.43,61.21 36.83,59.82 36.83,56.06 v2(37.11,55.78) 36.6,55.78 v2(36.2,55.37) v2(35.43,54.61) ; C47.2 v2(100.88,46.55) ; U9.1 v2(48.02,53.1) ; C83.2 v2(55.5,71.11) ; v2(86.49,55.63) 86.67,55.81 R44.2 ; TP4.1 v2(13.84,44.56) ; U5.2 v2(78.44,43.55) ; TP6.1 v2(134.1,75.06) ; U7.2 77.85,51.61 v2(78.13,51.33) 78.5,51.7 U7.3 ; R109.2 v2(9.66,73.53) ; TP10.1 v2(79.93,60.03)
  TOP w0.508: 36.79,10.27 J2.2 ; J2.2 35.98,11.08 ; J2.2 36.79,11.89 ; J2.2 37.61,11.08 ; C17.1 v2(44.2,52.78) ; J2.6 37.61,4.58 ; J2.6 35.98,4.58 ; J2.6 36.79,5.39 ; J2.6 36.79,3.77 ; J1.3 29.33,8.39 ; J1.3 28.52,7.58 ; J1.3 30.14,7.58 ; J1.3 29.33,6.77 ; R79.1 v2(143.12,31.5) ; J8.1 120.6,11.08 ; J8.1 118.97,11.08 ; J8.1 119.79,11.89 ; J8.1 119.79,10.27 ; 101.99,10.27 J8.2 ; J8.2 102.8,11.08 ; J8.2 101.99,11.89 ; J8.3 119.79,8.39 ; J8.3 118.97,7.58 ; J8.3 119.79,6.77 ; J8.3 120.6,7.58 ; 101.17,4.58 J8.6 ; J8.6 102.8,4.58 ; J8.6 101.99,3.77 ; J8.6 101.99,5.39 ; v1(136.92,49.46) v2(138.11,49.46) ; J7.4 76.72,8.39 ; J7.4 76.72,6.77 ; J7.4 75.91,7.58 ; J7.4 77.54,7.58 ; 59.8,25.4 J11.2 62.12,25.4 ; 28.52,11.08 J1.1 ; J1.1 29.33,11.89 ; J1.1 29.33,10.27 ; J1.1 30.14,11.08 ; J2.4 36.79,8.39 ; J2.4 35.98,7.58 ; J2.4 37.61,7.58 ; J2.4 36.79,6.77 ; 53.78,11.08 J2.1 ; J2.1 55.41,11.08 ; J2.1 54.59,11.89 ; J2.1 54.59,10.27 ; J7.6 77.54,4.58 ; J7.6 75.91,4.58 ; J7.6 76.72,3.77 ; J7.6 76.72,5.39 ; J1.5 30.14,5.58 ; J1.5 28.52,5.58 ; J1.5 29.33,4.77 ; J1.5 29.33,6.39 ; 54.59,4.77 J2.5 ; J2.5 55.41,5.58 ; J2.5 53.78,5.58 ; J2.5 54.59,6.39 ; J10.2 137.32,68.31 ; J10.2 135.93,66.93 ; J10.2 137.32,65.54 ; J10.2 138.71,66.93 ; 10.72,11.08 J1.2 ; J1.2 12.34,11.08 ; J1.2 11.53,11.89 ; J1.2 11.53,10.27 ; D6.A v2(115.52,47.5) ; BH8.1 60.96,7.85 ; BH8.1 63.73,5.08 ; BH8.1 58.19,5.08 ; 10.72,7.58 J1.4 ; J1.4 12.34,7.58 ; J1.4 11.53,6.77 ; J1.4 11.53,8.39 ; 101.99,6.77 J8.4 ; J8.4 101.99,8.39 ; J8.4 101.17,7.58 ; J8.4 102.8,7.58 ; C73.2 v2(111.64,42.29) ; J7.2 77.54,11.08 ; J7.2 76.72,10.27 ; J7.2 76.72,11.89 ; J7.2 75.91,11.08 ; 94.52,4.77 J7.5 ; J7.5 93.71,5.58 ; J7.5 94.52,6.39 ; J7.5 95.34,5.58 ; 118.97,5.58 J8.5 ; J8.5 119.79,6.39 ; J8.5 119.79,4.77 ; J8.5 120.6,5.58 ; R20.2 v2(50.55,57.79) ; J2.3 55.41,7.58 ; J2.3 53.78,7.58 ; J2.3 54.59,8.39 ; J2.3 54.59,6.77 ; J1.6 11.53,5.39 ; J1.6 12.34,4.58 ; J1.6 11.53,3.77 ; J1.6 10.72,4.58 ; J7.1 94.52,11.89 ; J7.1 94.52,10.27 ; J7.1 93.71,11.08 ; C72.2 v2(114.95,44.29) ; C74.2 v2(111.64,46.83) ; R21.2 v2(49.1,59.24) ; 94.52,6.77 J7.3 ; J7.3 94.52,8.39 ; J7.3 95.34,7.58 ; J7.3 93.71,7.58 ; R19.2 v2(45.87,55.33) ; Q1.2 v2(50.44,42.37) ; v2(14.58,53.85) C30.2 ; C30.2 v2(12.83,52.07) ; C30.2 v2(14.58,50.19) ; TP7.1 v2(16.75,5.08) ; C106.1 v2(142.63,36.7) ; Q7.3 v2(125.45,43.8) ; Q3.2 v2(50.44,46.69)
  L2_GND_1 w0.508: J5.7 107.73,64.07 ; J5.7 106.09,62.43 ; J5.7 106.09,64.07 ; J5.7 107.73,62.43 ; J2.6 37.38,5.16 ; J2.6 37.38,3.99 ; J2.6 36.21,3.99 ; J2.6 36.21,5.16 ; J5.12 83.41,70.44 ; J5.12 81.33,70.44 ; J5.12 81.33,72.53 ; J5.12 83.41,72.53 ; J3.13 25.61,62.94 ; J3.13 23.52,62.94 ; J3.13 25.61,65.03 ; J3.13 23.52,65.03 ; 96.33,72.53 J5.11 ; J5.11 98.42,72.53 ; J5.11 96.33,70.44 ; J5.11 98.42,70.44 ; BH3.1 7.05,74.23 ; BH3.1 3.11,78.17 ; BH3.1 7.05,78.17 ; BH3.1 3.11,74.23 ; BH2.1 144.21,74.23 ; BH2.1 140.27,74.23 ; BH2.1 140.27,78.17 ; BH2.1 144.21,78.17 ; 119.2,4.99 J8.5 ; J8.5 120.37,4.99 ; J8.5 119.2,6.16 ; J8.5 120.37,6.16 ; J6.4 75.03,67.41 ; J6.4 75.03,65.94 ; J6.4 73.56,67.41 ; J6.4 73.56,65.94 ; 96.33,65.03 J5.14 ; J5.14 98.42,62.94 ; J5.14 96.33,62.94 ; J5.14 98.42,65.03 ; J8.4 102.57,6.99 ; J8.4 102.57,8.16 ; J8.4 101.4,8.16 ; J8.4 101.4,6.99 ; J3.7 49.93,64.07 ; J3.7 48.29,64.07 ; J3.7 48.29,62.43 ; J3.7 49.93,62.43 ; J7.6 77.31,5.16 ; J7.6 76.14,5.16 ; J7.6 77.31,3.99 ; J7.6 76.14,3.99 ; J7.2 77.31,10.5 ; J7.2 76.14,11.66 ; J7.2 77.31,11.66 ; J7.2 76.14,10.5 ; 6.25,65.94 J4.4 ; J4.4 7.72,67.41 ; J4.4 7.72,65.94 ; J4.4 6.25,67.41 ; BH4.1 62.93,74.23 ; BH4.1 58.99,78.17 ; BH4.1 62.93,78.17 ; BH4.1 58.99,74.23 ; J2.2 37.38,11.66 ; J2.2 37.38,10.5 ; J2.2 36.21,10.5 ; J2.2 36.21,11.66 ; 119.2,8.16 J8.3 ; J8.3 120.37,8.16 ; J8.3 119.2,6.99 ; J8.3 120.37,6.99 ; J4.3 5.18,67.41 ; J4.3 5.18,65.94 ; J4.3 3.71,65.94 ; J4.3 3.71,67.41 ; 28.74,6.99 J1.3 ; J1.3 29.91,8.16 ; J1.3 29.91,6.99 ; J1.3 28.74,8.16 ; J7.4 77.31,6.99 ; J7.4 76.14,8.16 ; J7.4 76.14,6.99 ; J7.4 77.31,8.16 ; 69.15,74.23 BH5.1 ; BH5.1 73.09,78.17 ; BH5.1 69.15,78.17 ; BH5.1 73.09,74.23 ; 58.99,3.11 BH8.1 ; BH8.1 62.93,7.05 ; BH8.1 58.99,7.05 ; BH8.1 62.93,3.11 ; J2.3 55.18,8.16 ; J2.3 54.01,6.99 ; J2.3 55.18,6.99 ; J2.3 54.01,8.16 ; 101.4,5.16 J8.6 ; J8.6 102.57,3.99 ; J8.6 102.57,5.16 ; J8.6 101.4,3.99 ; 81.33,62.94 J5.13 ; J5.13 81.33,65.03 ; J5.13 83.41,62.94 ; J5.13 83.41,65.03 ; J1.6 12.11,3.99 ; J1.6 10.94,5.16 ; J1.6 10.94,3.99 ; J1.6 12.11,5.16 ; 10.94,8.16 J1.4 ; J1.4 12.11,6.99 ; J1.4 12.11,8.16 ; J1.4 10.94,6.99 ; J1.2 12.11,10.5 ; J1.2 10.94,10.5 ; J1.2 10.94,11.66 ; J1.2 12.11,11.66 ; J7.1 95.11,10.5 ; J7.1 93.94,10.5 ; J7.1 93.94,11.66 ; J7.1 95.11,11.66 ; J2.4 37.38,8.16 ; J2.4 37.38,6.99 ; J2.4 36.21,6.99 ; J2.4 36.21,8.16 ; J1.1 29.91,10.5 ; J1.1 28.74,11.66 ; J1.1 28.74,10.5 ; J1.1 29.91,11.66 ; 73.56,52.17 J6.16 ; J6.16 75.03,52.17 ; J6.16 73.56,50.7 ; J6.16 75.03,50.7 ; J6.3 72.49,67.41 ; J6.3 71.02,65.94 ; J6.3 71.02,67.41 ; J6.3 72.49,65.94 ; J4.1 5.18,68.48 ; J4.1 3.71,69.95 ; J4.1 5.18,69.95 ; J4.1 3.71,68.48 ; J11.2 61.79,26.23 ; J11.2 61.79,24.57 ; J11.2 60.13,26.23 ; J11.2 60.13,24.57 ; BH6.1 7.05,7.05 ; BH6.1 7.05,3.11 ; BH6.1 3.11,3.11 ; BH6.1 3.11,7.05 ; BH1.1 144.21,3.11 ; BH1.1 144.21,7.05 ; BH1.1 140.27,3.11 ; BH1.1 140.27,7.05 ; J6.6 75.03,63.4 ; J6.6 73.56,63.4 ; J6.6 73.56,64.87 ; J6.6 75.03,64.87 ; 69.15,7.05 BH7.1 ; BH7.1 73.09,7.05 ; BH7.1 73.09,3.11 ; BH7.1 69.15,3.11 ; J10.2 138.31,67.92 ; J10.2 136.33,65.94 ; J10.2 138.31,65.94 ; J10.2 136.33,67.92 ; J8.2 102.57,10.5 ; J8.2 101.4,10.5 ; J8.2 101.4,11.66 ; J8.2 102.57,11.66 ; J6.5 72.49,63.4 ; J6.5 72.49,64.87 ; J6.5 71.02,63.4 ; J6.5 71.02,64.87 ; 23.52,70.44 J3.12 ; J3.12 25.61,70.44 ; J3.12 23.52,72.53 ; J3.12 25.61,72.53 ; 119.2,10.5 J8.1 ; J8.1 119.2,11.66 ; J8.1 120.37,11.66 ; J8.1 120.37,10.5 ; 71.02,52.17 J6.15 ; J6.15 72.49,50.7 ; J6.15 71.02,50.7 ; J6.15 72.49,52.17 ; 28.74,6.16 J1.5 ; J1.5 28.74,4.99 ; J1.5 29.91,4.99 ; J1.5 29.91,6.16 ; J2.1 55.18,10.5 ; J2.1 54.01,11.66 ; J2.1 54.01,10.5 ; J2.1 55.18,11.66 ; 93.94,6.99 J7.3 ; J7.3 95.11,8.16 ; J7.3 93.94,8.16 ; J7.3 95.11,6.99 ; 93.94,4.99 J7.5 ; J7.5 93.94,6.16 ; J7.5 95.11,6.16 ; J7.5 95.11,4.99 ; J12.2 72.58,26.23 ; J12.2 72.58,24.57 ; J12.2 70.93,26.23 ; J12.2 70.93,24.57 ; 6.25,68.48 J4.2 ; J4.2 7.72,68.48 ; J4.2 7.72,69.95 ; J4.2 6.25,69.95 ; J6.1 72.49,69.95 ; J6.1 71.02,69.95 ; J6.1 71.02,68.48 ; J6.1 72.49,68.48 ; J3.14 40.61,62.94 ; J3.14 38.52,65.03 ; J3.14 38.52,62.94 ; J3.14 40.61,65.03 ; 38.52,72.53 J3.11 ; J3.11 38.52,70.44 ; J3.11 40.61,72.53 ; J3.11 40.61,70.44 ; J2.5 55.18,4.99 ; J2.5 55.18,6.16 ; J2.5 54.01,4.99 ; J2.5 54.01,6.16 ; 57.81,55.43 C86.2 ; C86.2 59.54,55.43 ; C86.2 59.54,53.7 ; C86.2 57.81,53.7 ; J6.2 75.03,69.95 ; J6.2 73.56,69.95 ; J6.2 73.56,68.48 ; J6.2 75.03,68.48
  L3_MIX_1 w0.508: J6.15 72.71,51.43 ; J6.15 71.75,50.48 ; J6.15 71.75,52.39 ; J6.15 70.8,51.43 ; 74.3,65.72 J6.4 ; J6.4 75.25,66.67 ; J6.4 73.34,66.67 ; J6.4 74.3,67.63 ; 73.34,69.22 J6.2 ; J6.2 74.3,70.17 ; J6.2 74.3,68.26 ; J6.2 75.25,69.22 ; 76.72,6.84 J7.4 ; J7.4 77.46,7.58 ; J7.4 76.72,8.32 ; J7.4 75.99,7.58 ; 119.05,7.58 J8.3 ; J8.3 120.53,7.58 ; J8.3 119.79,6.84 ; J8.3 119.79,8.32 ; 73.34,64.14 J6.6 ; J6.6 74.3,65.09 ; J6.6 75.25,64.14 ; J6.6 74.3,63.18 ; 49.11,62.18 J3.7 ; J3.7 48.04,63.25 ; J3.7 50.17,63.25 ; 93.79,5.58 J7.5 ; J7.5 95.26,5.58 ; J7.5 94.52,4.84 ; J7.5 94.52,6.32 ; 74.3,50.48 J6.16 ; J6.16 73.34,51.43 ; J6.16 75.25,51.43 ; J6.16 74.3,52.39 ; J3.13 25.95,63.98 ; J3.13 23.18,63.98 ; J3.13 24.57,62.6 ; J3.13 24.57,65.37 ; 38.18,63.98 J3.14 ; J3.14 39.57,65.37 ; J3.14 39.57,62.6 ; J3.14 40.95,63.98 ; 119.79,4.84 J8.5 ; J8.5 119.05,5.58 ; J8.5 120.53,5.58 ; J8.5 119.79,6.32 ; 95.99,63.98 J5.14 ; J5.14 98.76,63.98 ; J5.14 97.37,65.37 ; J5.14 97.37,62.6 ; 105.84,63.25 J5.7 ; J5.7 106.91,64.32 ; J5.7 107.98,63.25 ; J5.7 106.91,62.18 ; J6.5 72.71,64.14 ; J6.5 71.75,65.09 ; J6.5 70.8,64.14 ; J6.5 71.75,63.18 ; J6.1 72.71,69.22 ; J6.1 70.8,69.22 ; J6.1 71.75,70.17 ; J6.1 71.75,68.26 ; 137.32,65.62 J10.2 ; J10.2 138.63,66.93 ; J10.2 136.01,66.93 ; J10.2 137.32,68.24 ; J3.12 24.57,72.87 ; J3.12 25.95,71.48 ; J3.12 23.18,71.48 ; J3.12 24.57,70.1 ; J4.1 5.4,69.22 ; J4.1 3.49,69.22 ; J4.1 4.44,68.26 ; J4.1 4.44,70.17 ; J7.6 77.46,4.58 ; J7.6 76.72,3.84 ; J7.6 75.99,4.58 ; J7.6 76.72,5.32 ; 5.08,73.51 BH3.1 ; BH3.1 2.39,76.2 ; BH3.1 7.77,76.2 ; BH3.1 5.08,78.89 ; J8.4 102.73,7.58 ; J8.4 101.99,8.32 ; J8.4 101.25,7.58 ; J8.4 101.99,6.84 ; 97.37,70.1 J5.11 ; J5.11 98.76,71.48 ; J5.11 97.37,72.87 ; J5.11 95.99,71.48 ; 80.99,63.98 J5.13 ; J5.13 82.37,62.6 ; J5.13 82.37,65.37 ; J5.13 83.76,63.98 ; BH1.1 144.93,5.08 ; BH1.1 142.24,7.77 ; BH1.1 139.55,5.08 ; BH1.1 142.24,2.39 ; BH5.1 73.81,76.2 ; BH5.1 71.12,73.51 ; BH5.1 68.43,76.2 ; BH5.1 71.12,78.89 ; 71.12,2.39 BH7.1 ; BH7.1 68.43,5.08 ; BH7.1 71.12,7.77 ; BH7.1 73.81,5.08 ; 80.99,71.48 J5.12 ; J5.12 82.37,70.1 ; J5.12 82.37,72.87 ; J5.12 83.76,71.48 ; J7.3 94.52,8.32 ; J7.3 95.26,7.58 ; J7.3 93.79,7.58 ; J7.3 94.52,6.84 ; J6.3 71.75,67.63 ; J6.3 70.8,66.67 ; J6.3 71.75,65.72 ; J6.3 72.71,66.67 ; J3.11 40.95,71.48 ; J3.11 39.57,70.1 ; J3.11 39.57,72.87 ; J3.11 38.18,71.48 ; 6.03,69.22 J4.2 ; J4.2 7.94,69.22 ; J4.2 6.98,68.26 ; J4.2 6.98,70.17 ; BH2.1 142.24,78.89 ; BH2.1 144.93,76.2 ; BH2.1 139.55,76.2 ; BH2.1 142.24,73.51 ; 101.25,4.58 J8.6 ; J8.6 101.99,5.32 ; J8.6 102.73,4.58 ; J8.6 101.99,3.84
  L4_MIX_2 w0.508: 58.99,78.17 BH4.1 ; BH4.1 62.93,78.17 ; BH4.1 62.93,74.23 ; BH4.1 58.99,74.23 ; J10.2 138.31,67.92 ; J10.2 138.31,65.94 ; J10.2 136.33,65.94 ; J10.2 136.33,67.92 ; J3.14 40.61,65.03 ; J3.14 40.61,62.94 ; J3.14 38.52,65.03 ; J3.14 38.52,62.94 ; 140.27,74.23 BH2.1 ; BH2.1 140.27,78.17 ; BH2.1 144.21,78.17 ; BH2.1 144.21,74.23 ; 96.33,62.94 J5.14 ; J5.14 98.42,62.94 ; J5.14 98.42,65.03 ; J5.14 96.33,65.03 ; J5.13 83.41,65.03 ; J5.13 81.33,65.03 ; J5.13 81.33,62.94 ; J5.13 83.41,62.94 ; J5.12 83.41,70.44 ; J5.12 83.41,72.53 ; J5.12 81.33,72.53 ; J5.12 81.33,70.44 ; 23.52,65.03 J3.13 ; J3.13 25.61,65.03 ; J3.13 25.61,62.94 ; J3.13 23.52,62.94 ; 23.52,72.53 J3.12 ; J3.12 25.61,72.53 ; J3.12 25.61,70.44 ; J3.12 23.52,70.44 ; J3.7 49.93,62.43 ; J3.7 48.29,64.07 ; J3.7 48.29,62.43 ; 96.33,70.44 J5.11 ; J5.11 98.42,70.44 ; J5.11 96.33,72.53 ; J5.11 98.42,72.53 ; 38.52,70.44 J3.11 ; J3.11 40.61,72.53 ; J3.11 40.61,70.44 ; J3.11 38.52,72.53 ; 69.15,74.23 BH5.1 ; BH5.1 73.09,74.23 ; BH5.1 69.15,78.17 ; BH5.1 73.09,78.17 ; 57.81,53.7 C86.2 ; C86.2 57.81,55.43 ; C86.2 59.54,53.7 ; C86.2 59.54,55.43 ; 75.03,69.95 J6.2 73.56,69.95 ; 71.02,69.95 J6.1 72.49,69.95
  L5_GND_2 w0.508: 54.01,4.99 J2.5 ; J2.5 54.01,6.16 ; J2.5 55.18,4.99 ; J2.5 55.18,6.16 ; J2.6 37.38,5.16 ; J2.6 36.21,3.99 ; J2.6 37.38,3.99 ; J2.6 36.21,5.16 ; 70.93,24.57 J12.2 ; J12.2 70.93,26.23 ; J12.2 72.58,24.57 ; J12.2 72.58,26.23 ; 119.2,6.99 J8.3 ; J8.3 120.37,8.16 ; J8.3 120.37,6.99 ; J8.3 119.2,8.16 ; 28.74,11.66 J1.1 ; J1.1 29.91,10.5 ; J1.1 29.91,11.66 ; J1.1 28.74,10.5 ; 60.13,24.57 J11.2 ; J11.2 61.79,26.23 ; J11.2 60.13,26.23 ; J11.2 61.79,24.57 ; J5.7 107.73,64.07 ; J5.7 106.09,64.07 ; J5.7 107.73,62.43 ; J5.7 106.09,62.43 ; J5.13 83.41,62.94 ; J5.13 81.33,65.03 ; J5.13 81.33,62.94 ; J5.13 83.41,65.03 ; 69.15,74.23 BH5.1 ; BH5.1 69.15,78.17 ; BH5.1 73.09,78.17 ; BH5.1 73.09,74.23 ; 23.52,65.03 J3.13 ; J3.13 25.61,65.03 ; J3.13 23.52,62.94 ; J3.13 25.61,62.94 ; BH4.1 62.93,78.17 ; BH4.1 62.93,74.23 ; BH4.1 58.99,78.17 ; BH4.1 58.99,74.23 ; 6.25,65.94 J4.4 ; J4.4 7.72,67.41 ; J4.4 7.72,65.94 ; J4.4 6.25,67.41 ; 76.14,10.5 J7.2 ; J7.2 77.31,11.66 ; J7.2 76.14,11.66 ; J7.2 77.31,10.5 ; J5.12 83.41,70.44 ; J5.12 81.33,70.44 ; J5.12 83.41,72.53 ; J5.12 81.33,72.53 ; 10.94,11.66 J1.2 ; J1.2 12.11,10.5 ; J1.2 10.94,10.5 ; J1.2 12.11,11.66 ; J1.6 12.11,5.16 ; J1.6 12.11,3.99 ; J1.6 10.94,5.16 ; J1.6 10.94,3.99 ; 36.21,10.5 J2.2 ; J2.2 36.21,11.66 ; J2.2 37.38,11.66 ; J2.2 37.38,10.5 ; 71.02,69.95 J6.1 ; J6.1 71.02,68.48 ; J6.1 72.49,68.48 ; J6.1 72.49,69.95 ; 119.2,11.66 J8.1 ; J8.1 120.37,10.5 ; J8.1 119.2,10.5 ; J8.1 120.37,11.66 ; 57.81,55.43 C86.2 ; C86.2 57.81,53.7 ; C86.2 59.54,55.43 ; C86.2 59.54,53.7 ; BH6.1 7.05,7.05 ; BH6.1 3.11,3.11 ; BH6.1 3.11,7.05 ; BH6.1 7.05,3.11 ; BH1.1 144.21,3.11 ; BH1.1 140.27,3.11 ; BH1.1 140.27,7.05 ; BH1.1 144.21,7.05 ; J6.16 75.03,50.7 ; J6.16 75.03,52.17 ; J6.16 73.56,50.7 ; J6.16 73.56,52.17 ; 101.4,10.5 J8.2 ; J8.2 102.57,10.5 ; J8.2 102.57,11.66 ; J8.2 101.4,11.66 ; 101.4,3.99 J8.6 ; J8.6 102.57,3.99 ; J8.6 102.57,5.16 ; J8.6 101.4,5.16 ; 3.71,67.41 J4.3 ; J4.3 5.18,67.41 ; J4.3 3.71,65.94 ; J4.3 5.18,65.94 ; J3.14 40.61,65.03 ; J3.14 38.52,62.94 ; J3.14 40.61,62.94 ; J3.14 38.52,65.03 ; J2.4 37.38,6.99 ; J2.4 36.21,8.16 ; J2.4 36.21,6.99 ; J2.4 37.38,8.16 ; 10.94,8.16 J1.4 ; J1.4 12.11,6.99 ; J1.4 10.94,6.99 ; J1.4 12.11,8.16 ; J6.2 75.03,68.48 ; J6.2 75.03,69.95 ; J6.2 73.56,69.95 ; J6.2 73.56,68.48 ; J3.11 40.61,72.53 ; J3.11 38.52,72.53 ; J3.11 38.52,70.44 ; J3.11 40.61,70.44 ; J1.5 29.91,4.99 ; J1.5 28.74,4.99 ; J1.5 28.74,6.16 ; J1.5 29.91,6.16 ; 28.74,6.99 J1.3 ; J1.3 28.74,8.16 ; J1.3 29.91,6.99 ; J1.3 29.91,8.16 ; 58.99,3.11 BH8.1 ; BH8.1 58.99,7.05 ; BH8.1 62.93,7.05 ; BH8.1 62.93,3.11 ; J3.7 49.93,64.07 ; J3.7 49.93,62.43 ; J3.7 48.29,62.43 ; J3.7 48.29,64.07 ; 93.94,10.5 J7.1 ; J7.1 95.11,11.66 ; J7.1 95.11,10.5 ; J7.1 93.94,11.66 ; J7.5 95.11,6.16 ; J7.5 95.11,4.99 ; J7.5 93.94,4.99 ; J7.5 93.94,6.16 ; J6.4 75.03,67.41 ; J6.4 73.56,65.94 ; J6.4 75.03,65.94 ; J6.4 73.56,67.41 ; 101.4,8.16 J8.4 ; J8.4 102.57,6.99 ; J8.4 101.4,6.99 ; J8.4 102.57,8.16 ; J10.2 138.31,65.94 ; J10.2 136.33,67.92 ; J10.2 136.33,65.94 ; J10.2 138.31,67.92 ; J6.3 72.49,65.94 ; J6.3 71.02,67.41 ; J6.3 72.49,67.41 ; J6.3 71.02,65.94 ; 73.56,63.4 J6.6 ; J6.6 73.56,64.87 ; J6.6 75.03,64.87 ; J6.6 75.03,63.4 ; J5.11 98.42,72.53 ; J5.11 96.33,70.44 ; J5.11 98.42,70.44 ; J5.11 96.33,72.53 ; J5.14 98.42,62.94 ; J5.14 98.42,65.03 ; J5.14 96.33,62.94 ; J5.14 96.33,65.03 ; J8.5 120.37,6.16 ; J8.5 120.37,4.99 ; J8.5 119.2,6.16 ; J8.5 119.2,4.99 ; J2.3 55.18,8.16 ; J2.3 55.18,6.99 ; J2.3 54.01,6.99 ; J2.3 54.01,8.16 ; 69.15,7.05 BH7.1 ; BH7.1 73.09,3.11 ; BH7.1 69.15,3.11 ; BH7.1 73.09,7.05 ; J4.1 5.18,68.48 ; J4.1 3.71,69.95 ; J4.1 5.18,69.95 ; J4.1 3.71,68.48 ; 76.14,8.16 J7.4 ; J7.4 77.31,8.16 ; J7.4 76.14,6.99 ; J7.4 77.31,6.99 ; 71.02,63.4 J6.5 ; J6.5 72.49,63.4 ; J6.5 72.49,64.87 ; J6.5 71.02,64.87 ; 93.94,8.16 J7.3 ; J7.3 95.11,8.16 ; J7.3 93.94,6.99 ; J7.3 95.11,6.99 ; J2.1 55.18,10.5 ; J2.1 55.18,11.66 ; J2.1 54.01,11.66 ; J2.1 54.01,10.5 ; J7.6 77.31,5.16 ; J7.6 76.14,3.99 ; J7.6 76.14,5.16 ; J7.6 77.31,3.99 ; 3.11,74.23 BH3.1 ; BH3.1 7.05,78.17 ; BH3.1 7.05,74.23 ; BH3.1 3.11,78.17 ; J4.2 7.72,69.95 ; J4.2 6.25,68.48 ; J4.2 6.25,69.95 ; J4.2 7.72,68.48 ; 23.52,72.53 J3.12 ; J3.12 25.61,70.44 ; J3.12 23.52,70.44 ; J3.12 25.61,72.53 ; J6.15 72.49,52.17 ; J6.15 71.02,50.7 ; J6.15 72.49,50.7 ; J6.15 71.02,52.17 ; BH2.1 144.21,78.17 ; BH2.1 140.27,74.23 ; BH2.1 144.21,74.23 ; BH2.1 140.27,78.17
  BOTTOM w0.254: R43.2 93.93,56.75 v2(93.9,56.72) ; J12.2 J11.2 ; Q8.2 v2(51.8,40.24)
  BOTTOM w0.305: J2.A15 v2(41.09,20.61) ; J7.B18 v2(79.02,25.86) ; J1.A7 v2(22.23,20.61) ; J2.B15 v2(41.49,25.86) ; J7.A15 v2(81.02,20.61) ; J7.B7 v2(87.82,25.86) ; J2.A18 v2(38.69,20.61) ; J8.A18 v2(103.89,20.61) ; J2.B12 v2(43.89,25.86) ; J8.A4 115.09,20.8 v2(114.88,20.6) ; J7.A18 v2(78.62,20.61) ; J7.A7 v2(87.42,20.61) ; J7.B12 v2(83.82,25.86) ; J8.B4 v2(115.49,25.86) ; J1.B15 v2(16.23,25.86) ; J2.B1 v2(52.69,25.86) ; J8.A7 v2(112.69,20.61) ; J2.A7 v2(47.49,20.61) ; v2(49.89,20.19) 49.89,20.19 J2.A4 ; J7.A4 v2(89.82,20.61) ; J2.A1 52.29,20.19 v2(52.3,20.19) ; J1.B12 v2(18.63,25.86) ; J8.B1 v2(117.89,25.86) ; J8.B15 v2(106.69,25.86) ; J2.B4 v2(50.29,25.86) ; J8.A1 v2(117.49,20.61) ; J7.B1 v2(92.62,25.86) ; J1.A18 v2(13.43,20.61) ; J2.A12 v2(43.49,20.61) ; J7.B4 v2(90.22,25.86) ; J1.A4 v2(24.63,20.61) ; J2.B18 v2(39.09,25.86) ; J7.A1 v2(92.22,20.61) ; J1.A1 v2(27.03,20.61) ; J1.B7 v2(22.63,25.86) ; J2.B7 v2(47.89,25.86) ; J1.A12 v2(18.23,20.61) ; J1.B4 v2(25.03,25.86) ; J8.B7 v2(113.09,25.86) ; J8.A12 v2(108.69,20.61) ; J7.B15 v2(81.42,25.86) ; J8.A15 v2(106.29,20.61) ; J1.B1 v2(27.43,25.86) ; J1.A15 v2(15.83,20.61) ; J8.B18 v2(104.29,25.86) ; J8.B12 v2(109.09,25.86) ; J1.B18 v2(13.83,25.86) ; J7.A12 v2(83.42,20.61)
  BOTTOM w0.381: R61.2 124.99,43.8 v2(125.45,43.8) ; v2(127.05,19.96) Q6.2 ; R94.1 v2(56.39,49.52) ; U8.2 33.53,34.06 v2(33.83,34.37) 34.18,34.02 U8.3 ; C52.2 v2(92.08,42.25) ; v2(140.87,40.44) 140.13,40.44 C105.2 ; C42.1 78.31,44.17 78.44,44.04 v2(78.44,43.55) ; R89.1 v2(56.39,47.1) ; C41.2 C40.2 ; R96.1 v2(56.39,43.1)
  BOTTOM w0.508: J8.6 102.63,3.94 ; J8.6 101.35,3.94 ; J8.6 101.35,5.22 ; J8.6 102.63,5.22 ; 69.1,78.22 BH5.1 ; BH5.1 73.14,78.22 ; BH5.1 69.1,74.18 ; BH5.1 73.14,74.18 ; J2.3 55.23,8.22 ; J2.3 53.95,6.94 ; J2.3 55.23,6.94 ; J2.3 53.95,8.22 ; 70.96,64.93 J6.5 ; J6.5 72.55,64.93 ; J6.5 70.96,63.34 ; J6.5 72.55,63.34 ; J7.2 77.36,10.44 ; J7.2 76.09,11.72 ; J7.2 76.09,10.44 ; J7.2 77.36,11.72 ; J6.3 72.55,67.47 ; J6.3 70.96,65.88 ; J6.3 70.96,67.47 ; J6.3 72.55,65.88 ; 101.35,8.22 J8.4 ; J8.4 102.63,8.22 ; J8.4 101.35,6.94 ; J8.4 102.63,6.94 ; 53.95,10.44 J2.1 ; J2.1 53.95,11.72 ; J2.1 55.23,10.44 ; J2.1 55.23,11.72 ; J7.3 95.16,6.94 ; J7.3 93.89,6.94 ; J7.3 93.89,8.22 ; J7.3 95.16,8.22 ; J6.1 72.78,70.24 ; J6.1 70.73,68.19 ; J6.1 72.78,68.19 ; J6.1 70.73,70.24 ; 3.41,70.24 J4.1 ; J4.1 5.47,68.19 ; J4.1 3.41,68.19 ; J4.1 5.47,70.24 ; 101.35,11.72 J8.2 ; J8.2 101.35,10.44 ; J8.2 102.63,10.44 ; J8.2 102.63,11.72 ; 28.69,10.44 J1.1 ; J1.1 29.97,11.72 ; J1.1 29.97,10.44 ; J1.1 28.69,11.72 ; J1.5 29.97,6.22 ; J1.5 29.97,4.94 ; J1.5 28.69,6.22 ; J1.5 28.69,4.94 ; R93.1 v2(137.16,19.4) ; J6.16 75.09,50.64 ; J6.16 73.5,52.23 ; J6.16 73.5,50.64 ; J6.16 75.09,52.23 ; Q4.2 v2(133.34,13.11) ; 70.96,50.64 J6.15 ; J6.15 70.96,52.23 ; J6.15 72.55,50.64 ; J6.15 72.55,52.23 ; 38.47,70.39 J3.11 ; J3.11 38.47,72.58 ; J3.11 40.66,72.58 ; J3.11 40.66,70.39 ; J4.2 7.78,68.42 ; J4.2 7.78,70.01 ; J4.2 6.19,68.42 ; J4.2 6.19,70.01 ; 81.27,62.89 J5.13 ; J5.13 81.27,65.08 ; J5.13 83.47,65.08 ; BH6.1 7.1,7.1 ; BH6.1 3.06,7.1 ; BH6.1 7.1,3.06 ; BH6.1 3.06,3.06 ; 73.5,63.34 J6.6 ; J6.6 75.09,63.34 ; J6.6 75.09,64.93 ; J6.6 73.5,64.93 ; 28.69,6.94 J1.3 ; J1.3 28.69,8.22 ; J1.3 29.97,8.22 ; J1.3 29.97,6.94 ; J8.3 120.43,8.22 ; J8.3 119.15,6.94 ; J8.3 120.43,6.94 ; J8.3 119.15,8.22 ; 36.15,6.94 J2.4 ; J2.4 36.15,8.22 ; J2.4 37.43,6.94 ; J2.4 37.43,8.22 ; 76.09,8.22 J7.4 ; J7.4 77.36,6.94 ; J7.4 77.36,8.22 ; J7.4 76.09,6.94 ; J8.5 120.43,4.94 ; J8.5 119.15,4.94 ; J8.5 120.43,6.22 ; J8.5 119.15,6.22 ; 60.08,24.52 J11.2 ; J11.2 60.08,26.28 ; J11.2 61.84,26.28 ; J11.2 61.84,24.52 ; J6.4 75.09,67.47 ; J6.4 73.5,67.47 ; J6.4 73.5,65.88 ; J6.4 75.09,65.88 ; J4.3 5.24,67.47 ; J4.3 3.65,67.47 ; J4.3 5.24,65.88 ; J4.3 3.65,65.88 ; J5.12 83.47,70.39 ; J5.12 83.47,72.58 ; J5.12 81.27,72.58 ; J5.12 81.27,70.39 ; J1.2 12.17,11.72 ; J1.2 12.17,10.44 ; J1.2 10.89,11.72 ; J1.2 10.89,10.44 ; J2.5 55.23,4.94 ; J2.5 53.95,4.94 ; J2.5 55.23,6.22 ; J2.5 53.95,6.22 ; BH3.1 7.1,78.22 ; BH3.1 3.06,74.18 ; BH3.1 7.1,74.18 ; BH3.1 3.06,78.22 ; 93.89,4.94 J7.5 ; J7.5 93.89,6.22 ; J7.5 95.16,4.94 ; J7.5 95.16,6.22 ; 93.89,11.72 J7.1 93.89,10.44 ; 119.15,11.72 J8.1 ; J8.1 120.43,10.44 ; J8.1 120.43,11.72 ; J8.1 119.15,10.44 ; Q9.2 v2(134.21,16.8) ; 96.27,62.89 J5.14 ; J5.14 98.47,65.08 ; J5.14 96.27,65.08 ; J5.14 98.47,62.89 ; C29.2 v2(29.34,53.59) ; J5.11 98.47,70.39 ; J5.11 96.27,70.39 ; J5.11 96.27,72.58 ; J5.11 98.47,72.58 ; C25.2 27.66,49 27.66,48.87 v2(27.18,48.39) ; J4.4 7.78,67.47 ; J4.4 7.78,65.88 ; J4.4 6.19,65.88 ; J4.4 6.19,67.47 ; BH8.1 62.98,3.06 ; BH8.1 58.94,7.1 ; BH8.1 62.98,7.1 ; BH8.1 58.94,3.06 ; J1.6 12.17,5.22 ; J1.6 12.17,3.94 ; J1.6 10.89,3.94 ; J1.6 10.89,5.22 ; 36.15,10.44 J2.2 ; J2.2 37.43,10.44 ; J2.2 37.43,11.72 ; J2.2 36.15,11.72 ; R91.1 v2(137.17,20.83) ; Q5.2 v2(132.85,20.72) ; 57.76,55.48 C86.2 ; C86.2 59.59,53.65 ; C86.2 57.76,53.65 ; C86.2 59.59,55.48 ; BH2.1 144.26,74.18 ; BH2.1 140.22,74.18 ; BH2.1 140.22,78.22 ; BH2.1 144.26,78.22 ; J1.4 12.17,8.22 ; J1.4 10.89,8.22 ; J1.4 12.17,6.94 ; J1.4 10.89,6.94 ; J3.12 25.66,70.39 ; J3.12 23.47,70.39 ; J3.12 23.47,72.58 ; J3.12 25.66,72.58 ; 23.47,62.89 J3.13 ; J3.13 25.66,65.08 ; J3.13 23.47,65.08 ; J3.13 25.66,62.89 ; J5.7 107.78,62.38 ; J5.7 106.04,64.13 ; J5.7 106.04,62.38 ; J5.7 107.78,64.13 ; BH4.1 62.98,74.18 ; BH4.1 58.94,74.18 ; BH4.1 58.94,78.22 ; BH4.1 62.98,78.22 ; BH7.1 73.14,3.06 ; BH7.1 73.14,7.1 ; BH7.1 69.1,7.1 ; BH7.1 69.1,3.06 ; BH1.1 144.26,3.06 ; BH1.1 140.22,7.1 ; BH1.1 140.22,3.06 ; BH1.1 144.26,7.1 ; J7.6 77.36,5.22 ; J7.6 76.09,3.94 ; J7.6 77.36,3.94 ; J7.6 76.09,5.22 ; J6.2 75.09,68.42 ; J6.2 73.5,68.42 ; J6.2 73.5,70.01 ; J6.2 75.09,70.01 ; R95.1 v2(137.16,17.41) ; C23.2 v2(40.35,52.11) ; J3.7 49.98,62.38 ; J3.7 48.23,64.13 ; J3.7 48.23,62.38 ; Q2.2 v2(52.32,49.5) ; 36.15,5.22 J2.6 ; J2.6 36.15,3.94 ; J2.6 37.43,3.94 ; J2.6 37.43,5.22 ; R71.2 v2(19.43,29.96) ; J3.14 40.66,65.08 ; J3.14 38.47,65.08 ; J3.14 38.47,62.89 ; J3.14 40.66,62.89 ; v2(38.23,29.98) C27.2 ; 136.28,67.97 J10.2 ; J10.2 138.36,67.97 ; J10.2 136.28,65.89 ; J10.2 138.36,65.89 ; R72.2 v2(44.69,29.96)
  vias: v1(13.69,61.95) v1(13.69,61.06) v1(13.77,60.07) v1(14.4,63.07) v1(14.4,61.95) v1(14.4,60.63) v1(14.4,59.41) v1(15.01,60.07) v1(15.11,61.95) v1(15.11,61.05) v1(32.51,55.88) v1(32.77,48.89) v1(34.04,47.62) v1(34.16,48.89) v1(34.29,50.29) v1(34.42,55.88) v1(35.56,51.69) v1(35.56,48.89) v1(35.56,47.37) v1(35.56,46.1) v1(35.69,50.29) v1(36.96,50.29) v1(36.96,47.5) v1(37.08,48.89) v1(38.35,48.89) v1(83.5,54.41) v1(89.28,48.89) v1(90.55,47.62) v1(90.68,48.89) v1(90.8,50.29) v1(91.69,55.88) v1(92.08,51.69) v1(92.08,48.89) v1(92.08,47.37) v1(92.08,46.1) v1(92.2,50.29) v1(93.47,50.29) v1(93.47,47.5) v1(93.6,48.89) v1(94.87,48.89) v1(98.48,54.55) v1(100.56,52.47) v1(128.91,40.89) v1(129.92,40.89) v1(133.49,33.64) v1(134.33,31.94) v1(134.4,34.17) v1(134.45,41.82) v1(134.45,40.37) v1(134.45,38.92) v1(135.9,41.82) v1(135.9,40.37) v1(135.9,38.92) v1(137.35,41.82) v1(137.35,40.37) v1(137.35,38.92) v2(2.16,73.91) v2(2.16,72.64) v2(2.16,71.25) v2(2.16,69.72) v2(2.16,68.2) v2(4.7,72.01) v2(7.75,72.01) v2(9.14,48.26) v2(9.27,63.63) v2(11.18,79.12) v2(12.32,33.4) v2(12.62,44.32) v2(12.78,46.35) v2(12.75,41.3) v2(12.85,38.73) v2(13.18,34.44) v2(13.43,18.21) v2(13.82,58.67) v2(13.82,57.1) v2(13.77,55.75) v2(13.84,29.59) v2(14.4,56.31) v2(14.81,58.67) v2(14.94,30.47) v2(15.77,43.59) v2(15.83,19.81) v2(16.26,79.12) v2(18.23,19.81) v2(19.62,43.3) v2(20.41,30.61) v2(20.41,29.59) v2(21.34,79.12) v2(22.23,18.21) v2(23.11,48.51) v2(23.88,30.47) v2(24.63,19.81) v2(24.93,29.59) v2(25.18,60.28) v2(25.21,59.51) v2(25.25,61.03) v2(25.53,58.82) v2(25.64,61.69) v2(26.05,70.05) v2(26.04,69.21) v2(26.12,58.34) v2(26.28,62.11) v2(26.42,79.12) v2(26.63,68.6) v2(26.66,70.64) v2(26.72,60.12) v2(26.87,58.18) v2(27.03,62.24) v2(27.03,19.81) v2(27.17,60.72) v2(27.31,68.29) v2(27.31,67.53) v2(27.31,66.76) v2(27.31,66) v2(27.31,65.24) v2(27.31,64.48) v2(27.31,63.72) v2(27.31,62.95) v2(27.32,59.68) v2(27.31,57.56) v2(27.33,55.87) v2(27.43,28.26) v2(27.53,70.71) v2(27.89,60.99) v2(28.04,59.42) v2(28.45,61.5) v2(28.55,70.71) v2(28.57,58.88) v2(28.83,68.29) v2(28.83,67.53) v2(28.83,66.76) v2(28.83,66) v2(28.83,65.24) v2(28.83,64.48) v2(28.83,63.72) v2(28.83,62.95) v2(28.77,62.19) v2(28.82,58.16) v2(28.87,45.43) v2(29.05,54.31) v2(29.34,43.76) v2(29.34,25.01) v2(29.47,70.64) v2(29.51,68.6) v2(29.5,57.42) v2(30.08,70.05) v2(30.09,69.21) v2(30.16,56.82) v2(30.18,42.44) v2(30.77,56.17) v2(31.15,25.09) v2(31.5,79.12) v2(31.67,42.48) v2(33.16,42.56) v2(34.05,70.05) v2(34.04,69.21) v2(34.63,68.6) v2(34.66,70.64) v2(35.31,68.29) v2(35.31,67.53) v2(35.31,66.76) v2(35.31,66) v2(35.31,65.24) v2(35.31,64.48) v2(35.31,63.72) v2(35.33,62.95) v2(35.41,43.11) v2(35.56,70.71) v2(35.54,62.22) v2(35.93,61.57) v2(36.46,61.01) v2(36.58,79.12) v2(36.6,70.71) v2(36.83,68.29) v2(36.83,67.53) v2(36.83,66.76) v2(36.83,66) v2(36.83,65.24) v2(36.83,64.48) v2(36.83,63.72) v2(36.89,62.96) v2(36.99,60.48) v2(37.3,62.32) v2(37.49,70.71) v2(37.57,68.53) v2(37.53,59.94) v2(37.82,54.86) v2(37.84,61.78) v2(37.99,42.47) v2(38,37.85) v2(37.97,35.43) v2(38.07,59.4) v2(38.15,70.05) v2(38.17,69.21) v2(38.38,61.24) v2(38.61,58.86) v2(38.69,18.21) v2(38.92,60.7) v2(39.15,58.32) v2(39.2,29.59) v2(39.46,60.16) v2(39.5,30.61) v2(39.69,57.78) v2(39.8,42.16) v2(39.99,59.62) v2(40.23,57.24) v2(40.49,55.57) v2(40.53,59.08) v2(41.07,58.55) v2(41.09,18.21) v2(41.15,56.26) v2(41.41,44.16) v2(41.51,42.61) v2(41.66,79.12) v2(41.66,57.91) v2(41.68,29.59) v2(41.96,46.96) v2(42.35,53.85) v2(42.8,32.05) v2(42.8,30.53) v2(43.08,54.51) v2(43.49,19.81) v2(44.02,46.99) v2(44.32,45.21) v2(45.04,46.96) v2(45.67,30.61) v2(45.67,29.59) v2(46.74,79.12) v2(47.49,18.21) v2(48.01,53.98) v2(48.46,30.61) v2(49.4,30.61) v2(50.29,26.66) v2(51.82,79.12) v2(51.94,69.72) v2(51.96,68.83) v2(52.7,26.66) v2(52.83,52.7) v2(52.96,69.71) v2(53.09,63.63) v2(53.09,62.36) v2(53.98,62.99) v2(54.1,69.72) v2(54.86,63.75) v2(54.86,62.36) v2(56.9,79.12) v2(59.82,70.99) v2(60.32,67.95) v2(60.58,70.61) v2(60.58,69.6) v2(61.72,70.61) v2(61.72,69.65) v2(62.74,69.65) v2(63.88,70.74) v2(63.88,69.63) v2(64.52,68.83) v2(64.52,67.69) v2(64.64,70.23) v2(75.69,43.28) v2(77.75,29.31) v2(78.89,40.72) v2(79.02,27.68) v2(79.63,16.89) v2(80.64,16.89) v2(80.9,33.1) v2(81.03,59.19) v2(81.07,58.43) v2(81.22,51.4) v2(81.32,59.89) v2(81.43,27.68) v2(81.42,26.66) v2(81.48,57.78) v2(81.79,16.85) v2(81.92,60.36) v2(82.17,57.46) v2(82.17,48.23) v2(82.51,60.84) v2(82.51,56.78) v2(82.63,56.03) v2(82.65,61.59) v2(82.8,16.89) v2(82.86,59.05) v2(83.02,62.25) v2(83.11,55.37) v2(83.52,59.42) v2(83.45,58.56) v2(83.55,62.8) v2(83.72,32.33) v2(83.83,26.66) v2(83.86,70.05) v2(83.84,69.21) v2(83.92,60.07) v2(83.89,57.94) v2(83.99,60.83) v2(83.98,57.19) v2(84.09,63.34) v2(84.16,56.44) v2(84.16,51.25) v2(84.15,42.47) v2(84.34,61.51) v2(84.47,70.64) v2(84.43,68.6) v2(84.63,63.88) v2(84.61,15.32) v2(84.88,62.05) v2(85.08,64.5) v2(85.1,45.62) v2(85.14,68.31) v2(85.14,67.54) v2(85.14,66.78) v2(85.14,66.02) v2(85.14,65.26) v2(85.34,70.71) v2(85.42,62.58) v2(85.78,48.72) v2(85.85,32.26) v2(85.95,63.13) v2(85.98,34.52) v2(85.98,16.89) v2(86.06,47.45) v2(86.18,44.71) v2(86.41,70.71) v2(86.37,63.77) v2(86.61,68.31) v2(86.61,67.54) v2(86.61,66.78) v2(86.61,66.02) v2(86.61,65.26) v2(86.58,64.5) v2(87,16.89) v2(87.28,70.64) v2(87.31,68.6) v2(87.27,43.77) v2(87.76,33.02) v2(87.82,26.66) v2(87.88,70.05) v2(87.9,69.21) v2(88.15,42.63) v2(88.19,16.85) v2(89.2,16.89) v2(89.38,40.23) v2(89.59,42.75) v2(89.94,37.46) v2(90.22,27.68) v2(90.23,26.66) v2(91.82,39.6) v2(91.86,70.05) v2(91.84,69.21) v2(92.22,18.21) v2(92.47,70.64) v2(92.43,68.6) v2(92.63,27.68) v2(93.14,68.31) v2(93.14,67.54) v2(93.14,66.78) v2(93.14,66.02) v2(93.16,65.26) v2(93.26,64.5) v2(93.37,70.71) v2(93.45,63.77) v2(93.72,63.05) v2(94.01,13.59) v2(94.07,62.38) v2(94.11,31.52) v2(94.36,70.71) v2(94.49,61.74) v2(94.61,68.31) v2(94.61,67.54) v2(94.61,66.78) v2(94.61,66.02) v2(94.64,65.26) v2(94.77,64.51) v2(94.89,42.77) v2(95.01,63.79) v2(94.98,61.16) v2(95,38.2) v2(95.33,70.71) v2(95.35,68.53) v2(95.35,63.1) v2(95.52,60.62) v2(95.79,62.48) v2(95.73,21.01) v2(95.96,70.08) v2(95.96,69.22) v2(96.06,60.08) v2(96.3,61.92) v2(96.3,42.36) v2(96.6,59.54) v2(96.84,61.38) v2(96.93,15.88) v2(96.97,55.96) v2(97.14,59) v2(97.26,53.47) v2(97.38,60.84) v2(97.61,43.08) v2(97.67,58.46) v2(97.69,55.26) v2(97.92,60.3) v2(98.21,57.92) v2(98.46,59.76) v2(98.68,44.07) v2(98.75,57.39) v2(99,59.22) v2(99.29,56.85) v2(99.41,47) v2(99.52,15.93) v2(99.54,58.69) v2(99.72,45.14) v2(99.82,56.29) v2(99.89,55.54) v2(99.89,54.77) v2(100.07,58.15) v2(100.61,57.61) v2(100.87,53.38) v2(100.91,20.8) v2(101.1,57.02) v2(101.28,54.02) v2(101.35,56.3) v2(101.37,55.54) v2(101.37,54.78) v2(101.88,14.25) v2(103.33,51.97) v2(104.29,26.66) v2(104.89,16.89) v2(105.91,16.89) v2(106.69,27.68) v2(106.69,26.66) v2(107.05,16.85) v2(108.07,16.89) v2(109.09,27.68) v2(111.12,52.58) v2(111.12,51.05) v2(111.12,49.91) v2(111.24,16.89) v2(111.76,66.29) v2(111.76,51.82) v2(112.26,16.89) v2(112.39,51.05) v2(112.39,49.91) v2(112.52,65.41) v2(113.03,38.1) v2(113.03,37.08) v2(113.03,36.07) v2(113.09,26.66) v2(113.45,16.85) v2(113.55,67.49) v2(113.54,66.29) v2(113.54,49.91) v2(114.3,36.07) v2(114.47,16.89) v2(114.68,67.31) v2(114.68,48.77) v2(114.68,46.23) v2(114.81,49.91) v2(115.49,27.68) v2(115.49,26.66) v2(115.7,36.07) v2(115.82,49.91) v2(116.59,48.77) v2(116.59,46.23) v2(116.71,52.32) v2(116.71,51.31) v2(116.71,50.29) v2(116.84,38.35) v2(116.84,37.21) v2(116.84,36.07) v2(117.49,18.21) v2(117.89,27.68) v2(120.4,65.79) v2(120.4,64.64) v2(120.4,63.63) v2(120.4,62.86) v2(120.4,61.85) v2(121.41,65.79) v2(121.41,64.64) v2(121.41,63.63) v2(121.41,62.86) v2(121.41,61.85) v2(122.43,64.64) v2(122.43,63.63) v2(122.43,62.86) v2(122.43,61.85) v2(123.44,64.64) v2(123.44,63.63) v2(123.44,62.86) v2(123.44,61.85) v2(123.85,45.93) v2(124.46,64.64) v2(124.46,63.63) v2(124.46,62.86) v2(124.46,61.85) v2(125.98,44.32) v2(125.98,43.33) v2(129.41,69.6) v2(129.41,68.45) v2(129.41,67.18) v2(129.54,24.89) v2(129.54,20.83) v2(129.94,47.26) v2(130.3,67.82) v2(130.3,66.55) v2(130.43,29.21) v2(130.43,25.9) v2(130.94,69.6) v2(130.94,68.58) v2(130.94,24.26) v2(130.94,22.99) v2(130.94,21.84) v2(131.59,45.71) v2(131.95,29.21) v2(131.95,25.9) v2(132.08,22.99) v2(132.21,69.6) v2(132.21,68.58) v2(132.46,24.26) v2(133.35,31.68) v2(133.35,29.21) v2(133.35,28.07) v2(133.35,27.05) v2(133.35,25.91) v2(133.48,69.6) v2(133.48,68.58) v2(133.73,24.26) v2(134.11,67.95) v2(134.11,66.67) v2(134.19,30.91) v2(135.38,69.6) v2(135.38,68.33) v2(135.38,67.06) v2(135.38,65.79) v2(136.22,54.69) v2(136.24,53.77) v2(137.49,54.71) v2(137.49,53.77) v2(138.68,54.74) v2(138.68,53.72) v2(138.68,52.83) v2(138.68,51.94) v2(138.68,50.93) v2(139.95,23.24) v2(141.35,23.24) v2(142.11,29.84) v2(142.11,28.83) v2(142.11,27.94) v2(142.11,26.92) v2(142.11,25.78) v2(142.11,24.77) v2(142.11,23.88) v2(142.75,23.24) v2(143.26,29.84) v2(143.26,28.83) v2(143.26,27.81) v2(143.26,26.8) v2(143.26,25.78) v2(143.26,24.77) v2(143.26,23.88)
